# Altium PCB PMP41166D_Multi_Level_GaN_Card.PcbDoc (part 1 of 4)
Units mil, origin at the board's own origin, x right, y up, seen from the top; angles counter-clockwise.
Board outline 3221.72 x 1840 mil, 6 copper layers (Top Layer, Signal Layer 1, Signal Layer 2, Signal Layer 3, Signal Layer 4, Bottom Layer), stack 51.8 mil thick; 155 components, 123 nets, 580 pads, 278 vias.
Unrouted connection lines stored in the file: 2.
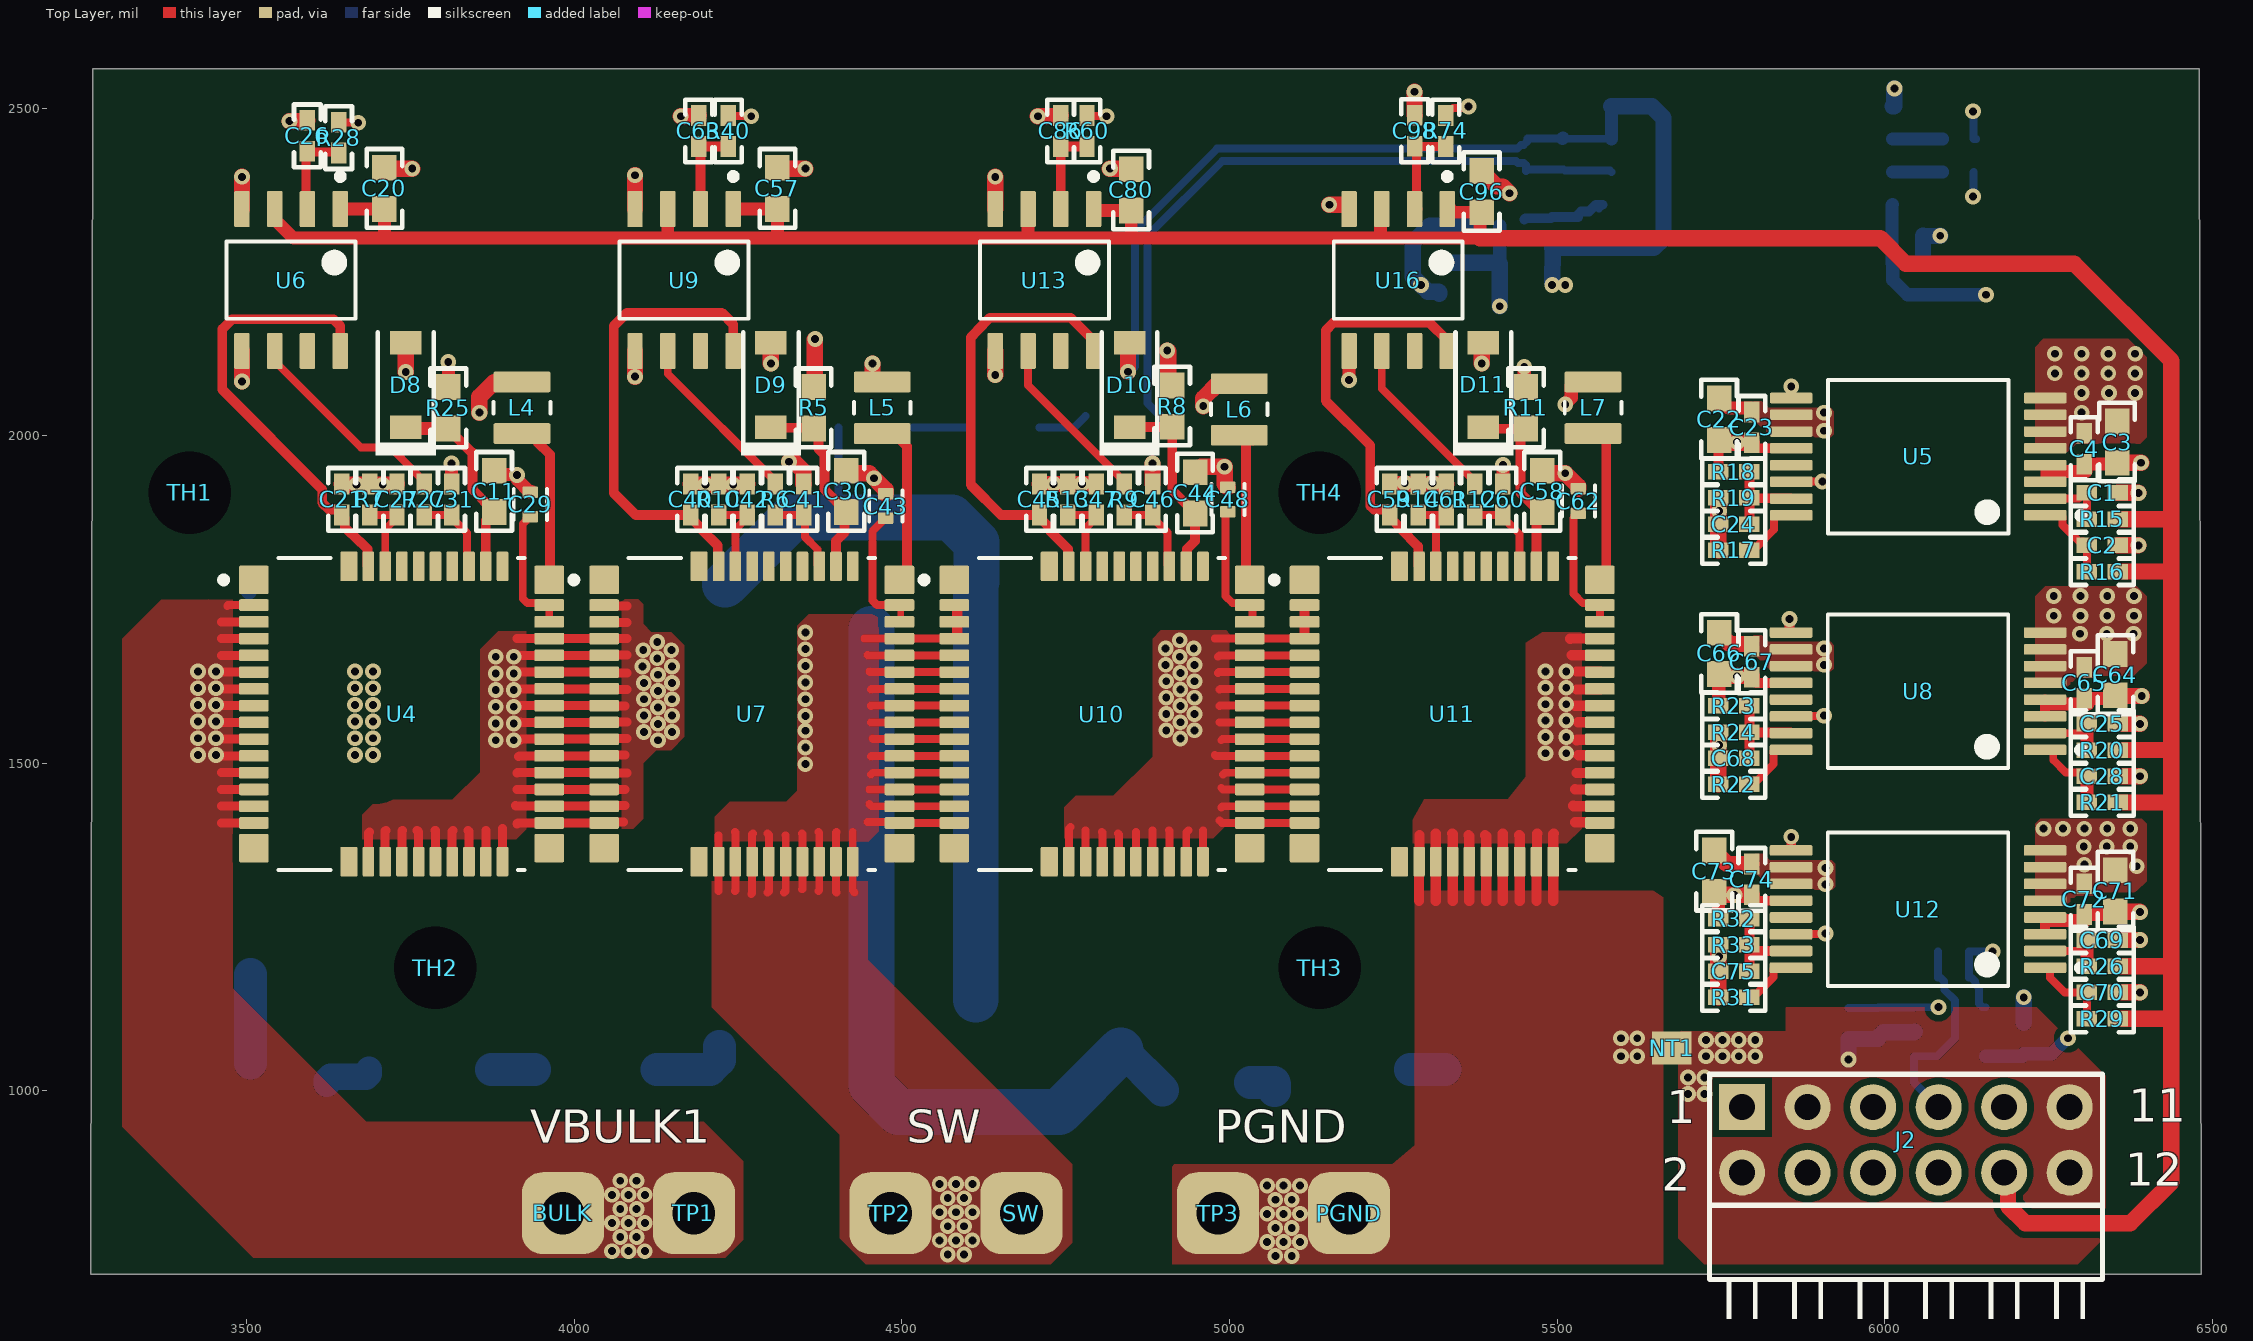
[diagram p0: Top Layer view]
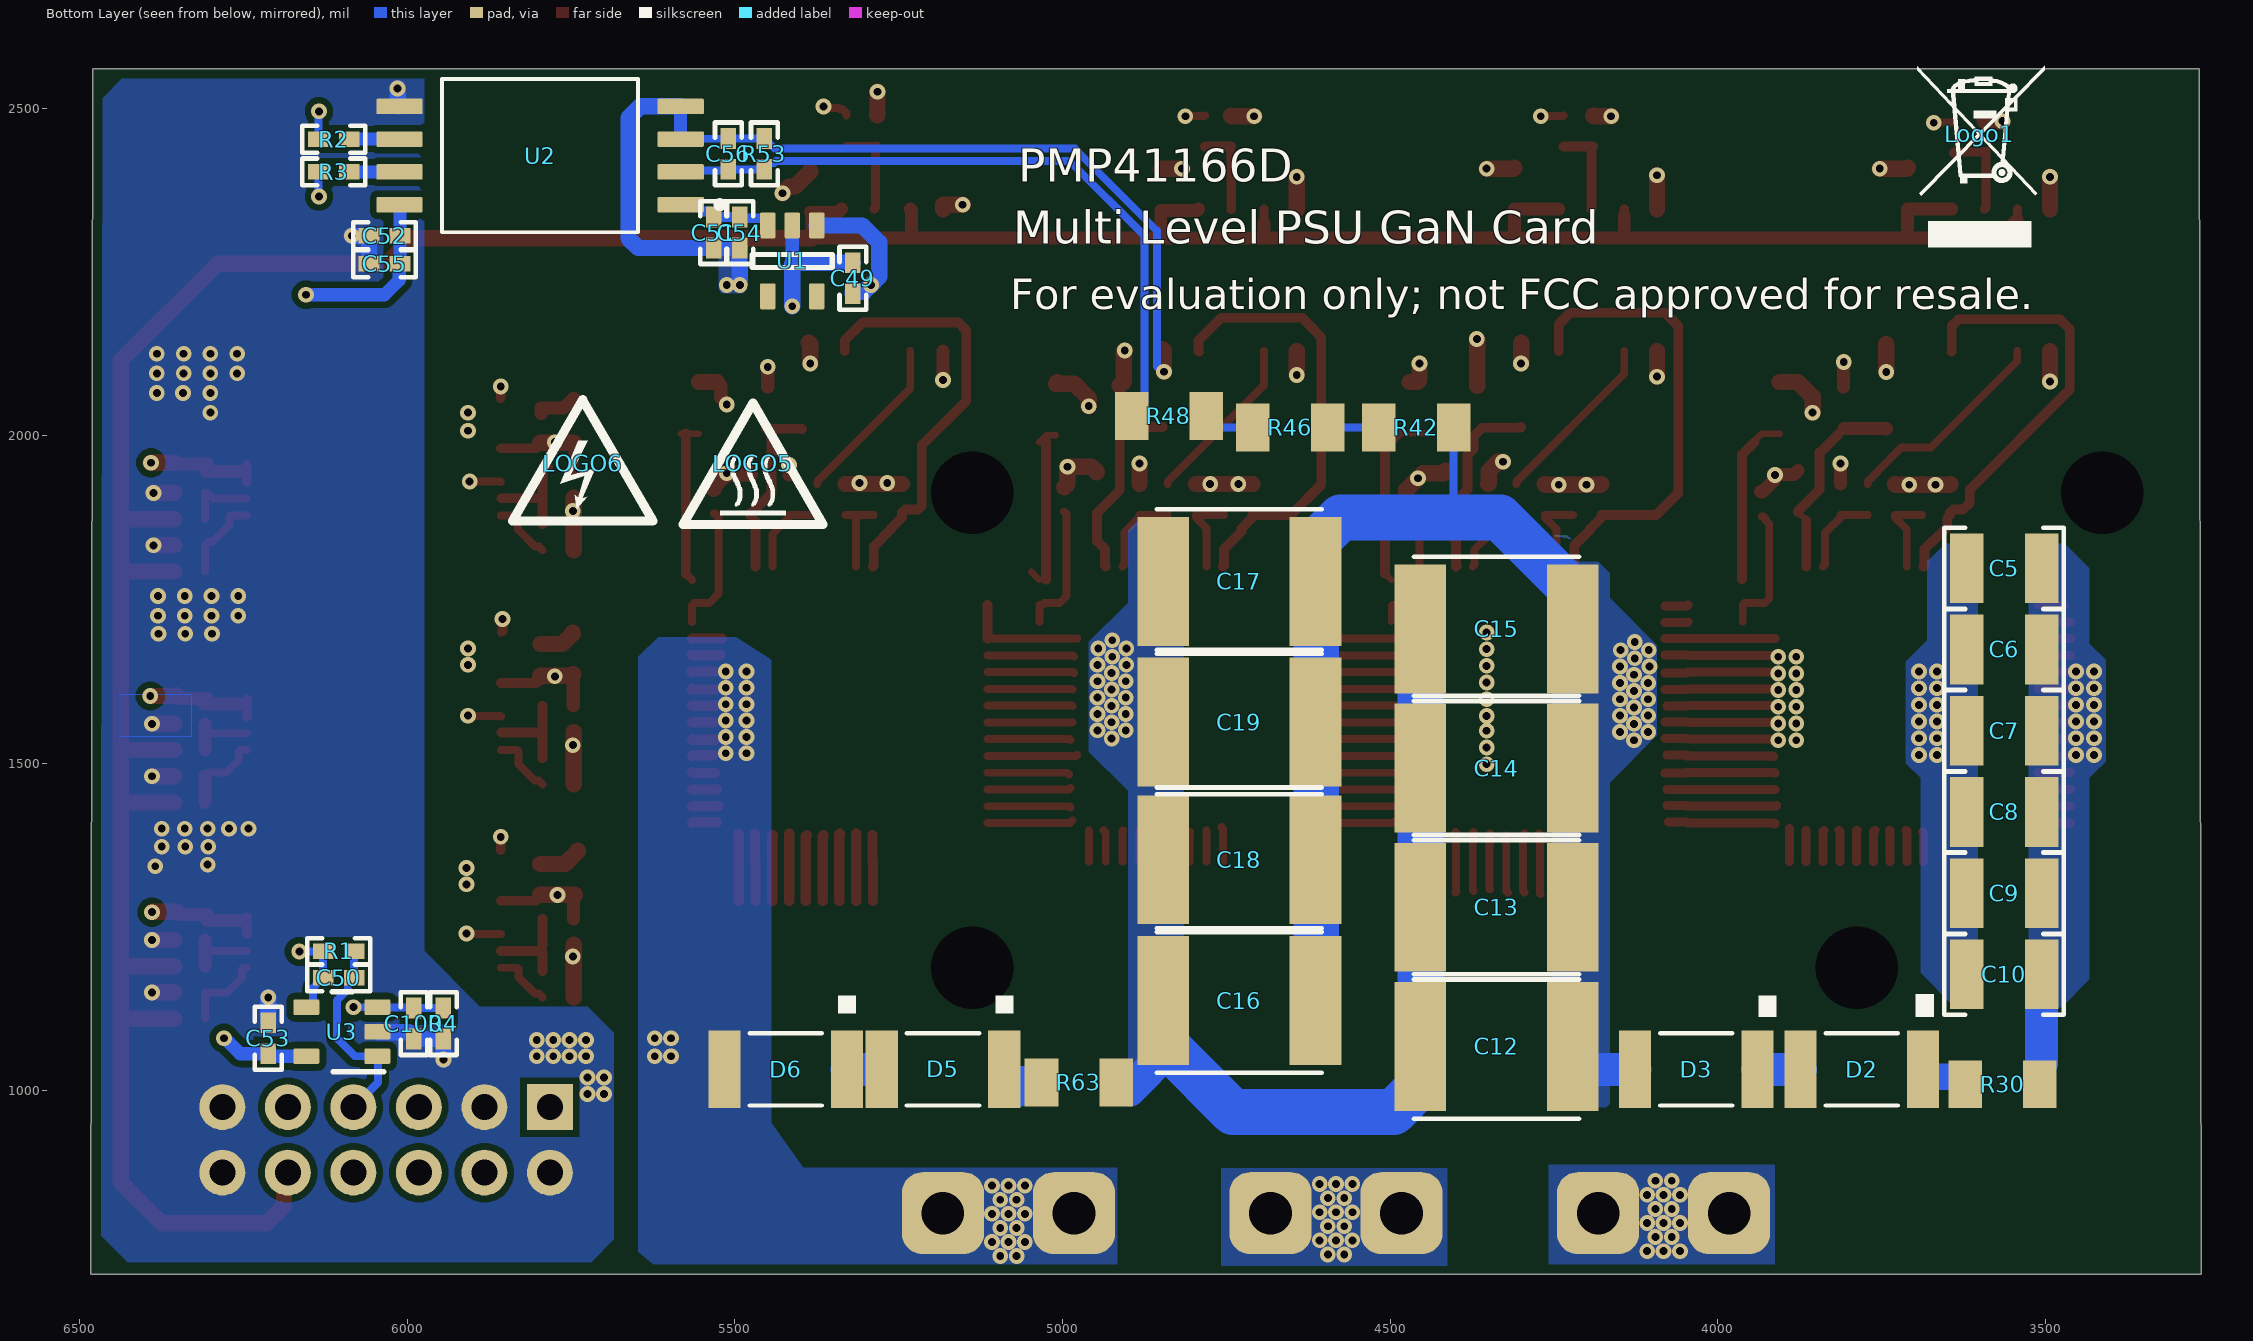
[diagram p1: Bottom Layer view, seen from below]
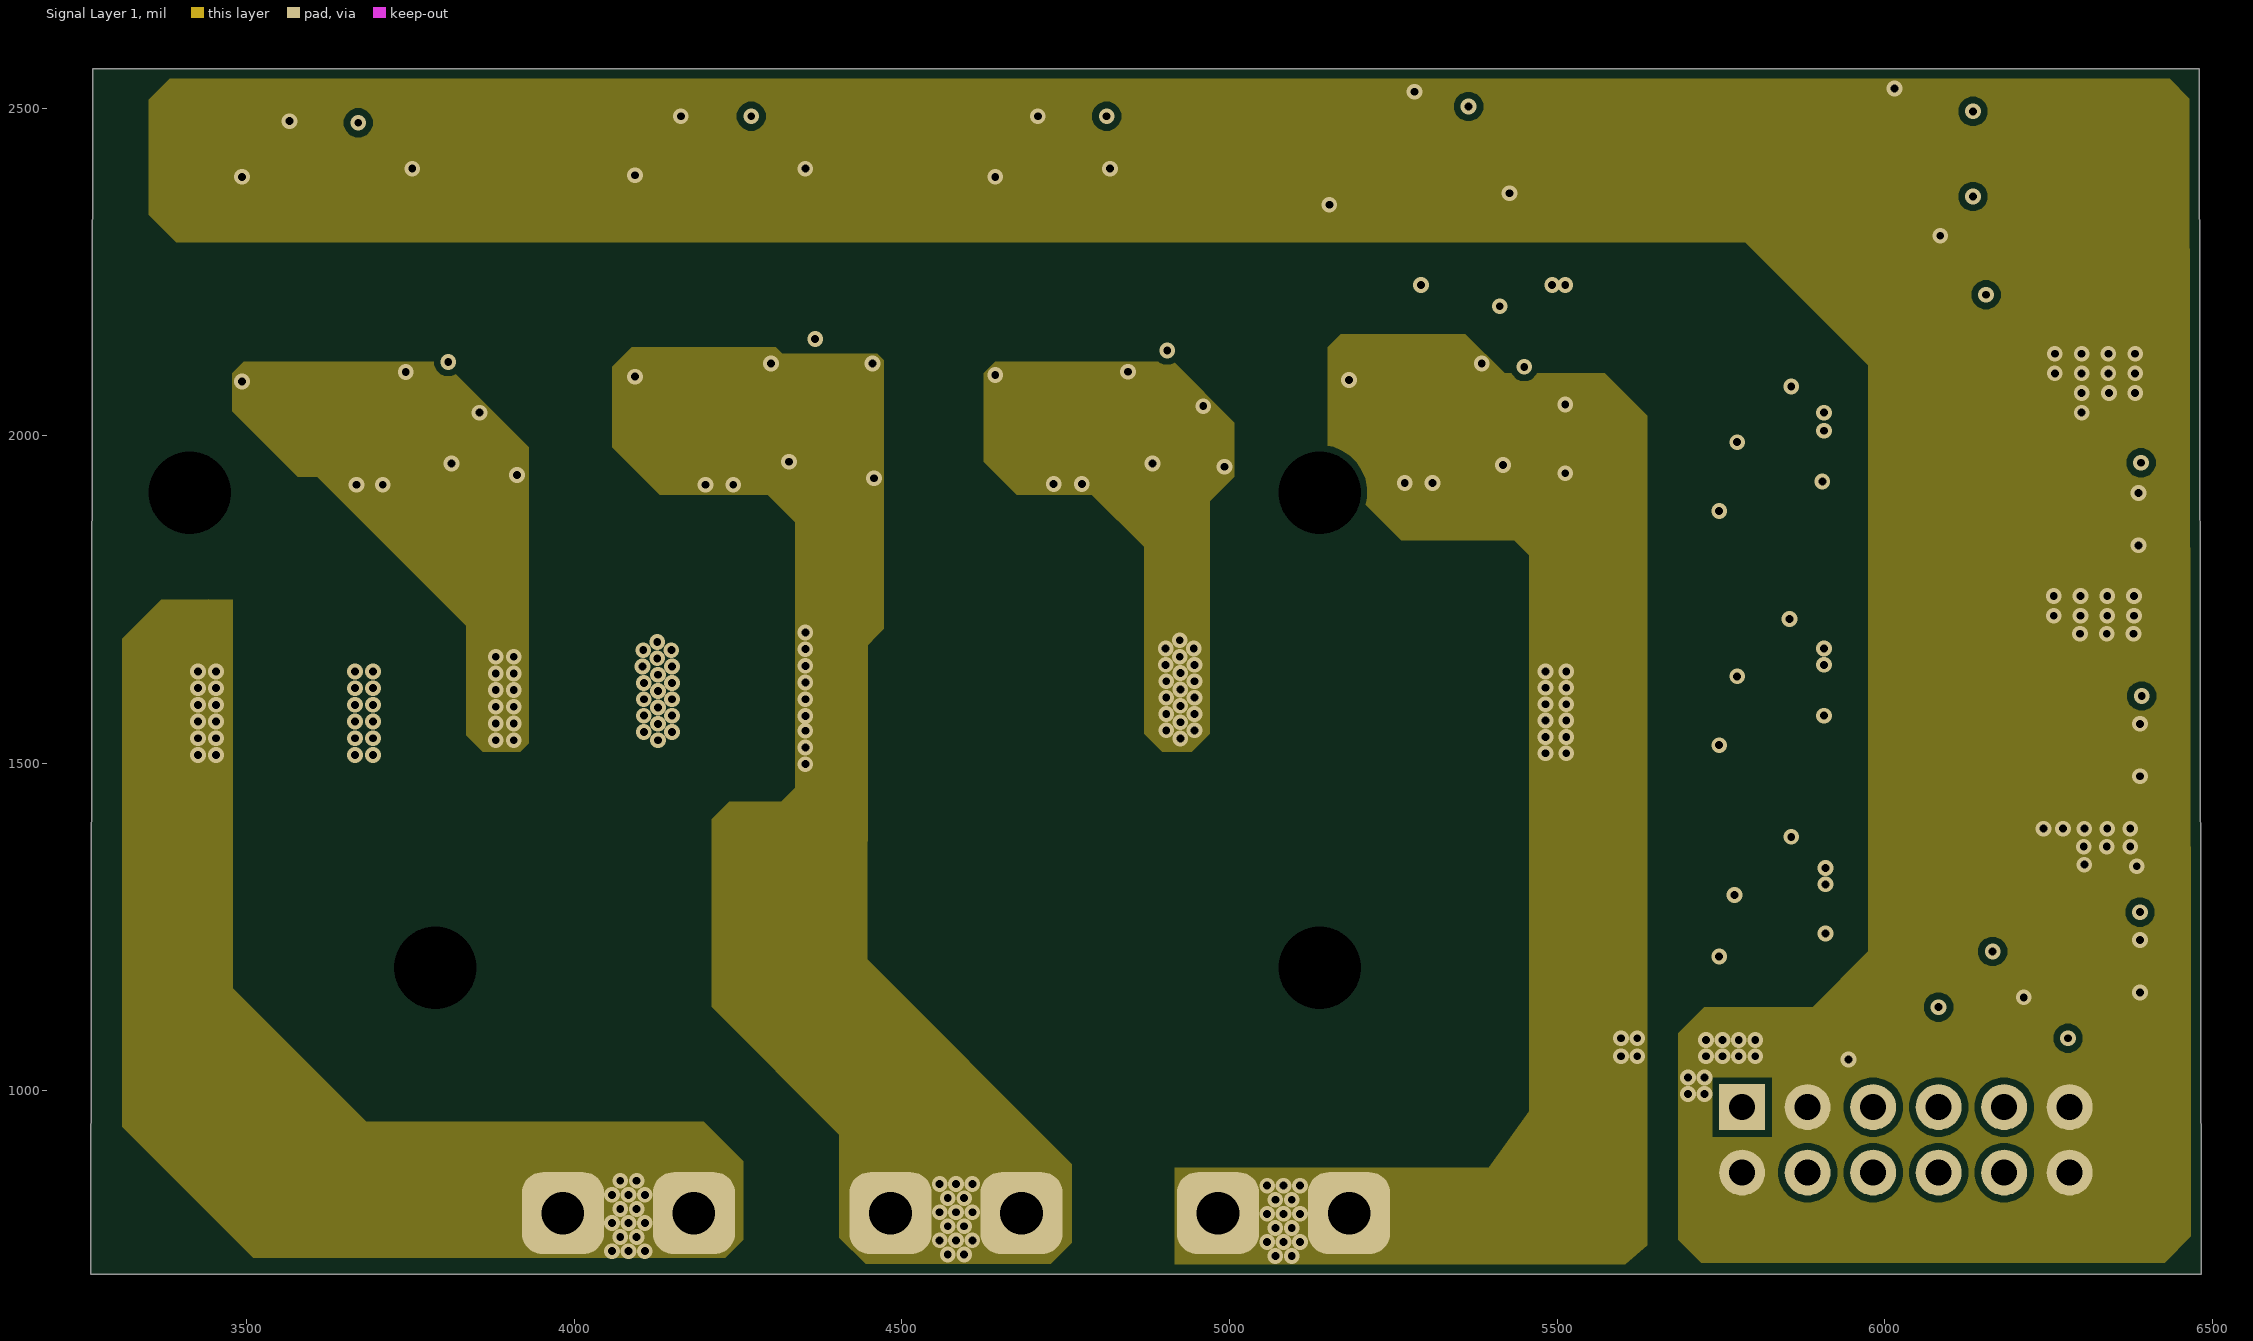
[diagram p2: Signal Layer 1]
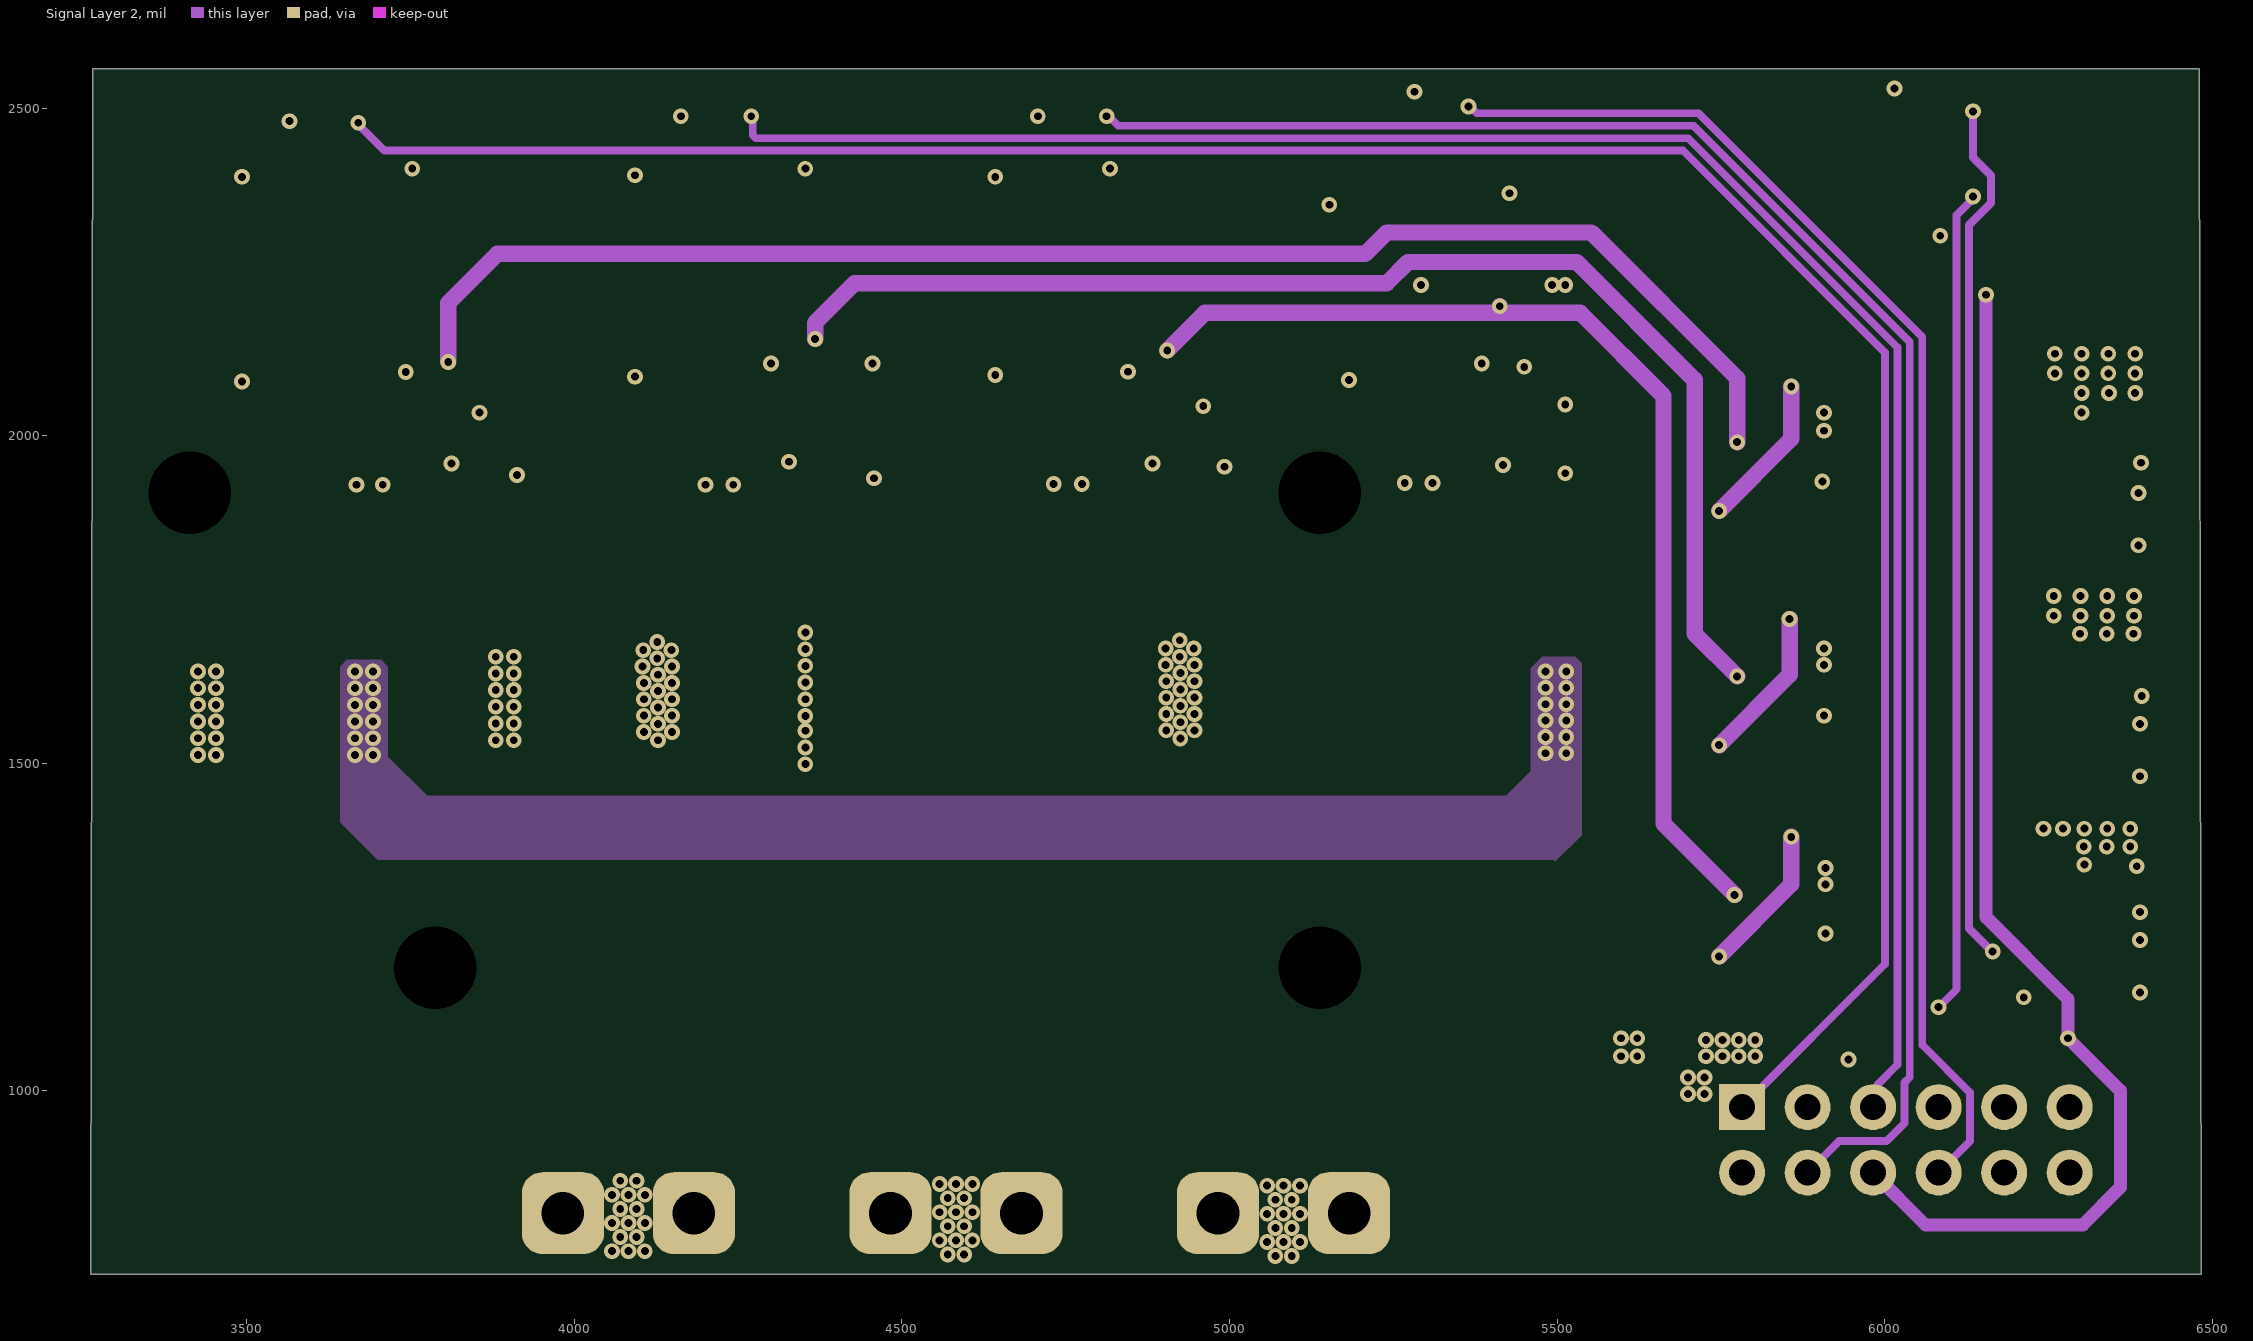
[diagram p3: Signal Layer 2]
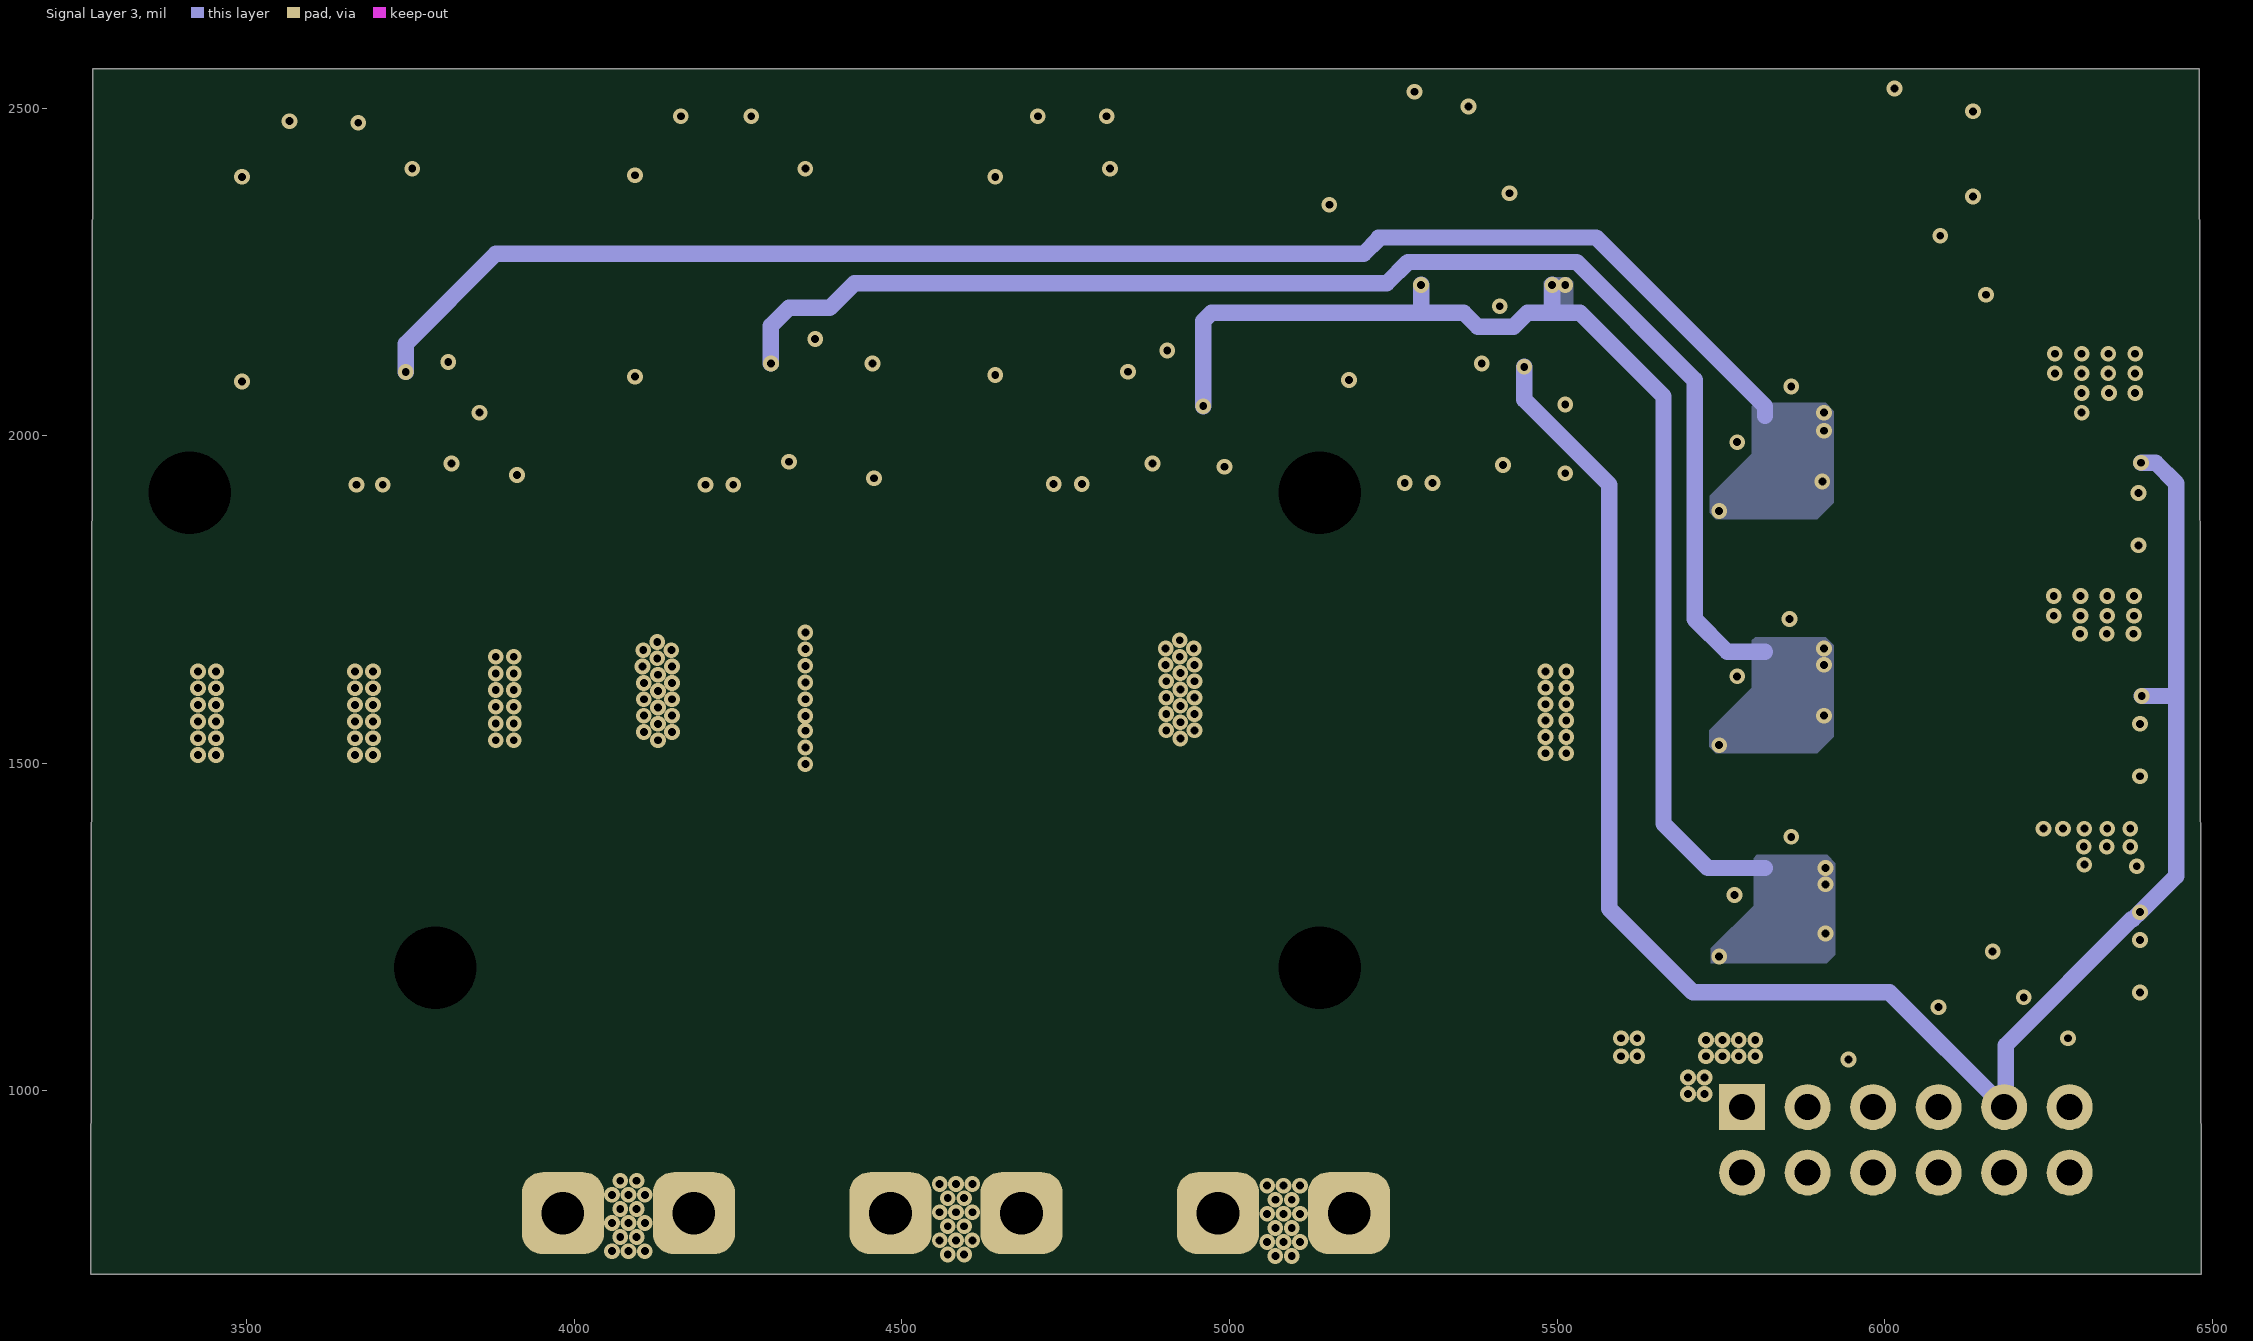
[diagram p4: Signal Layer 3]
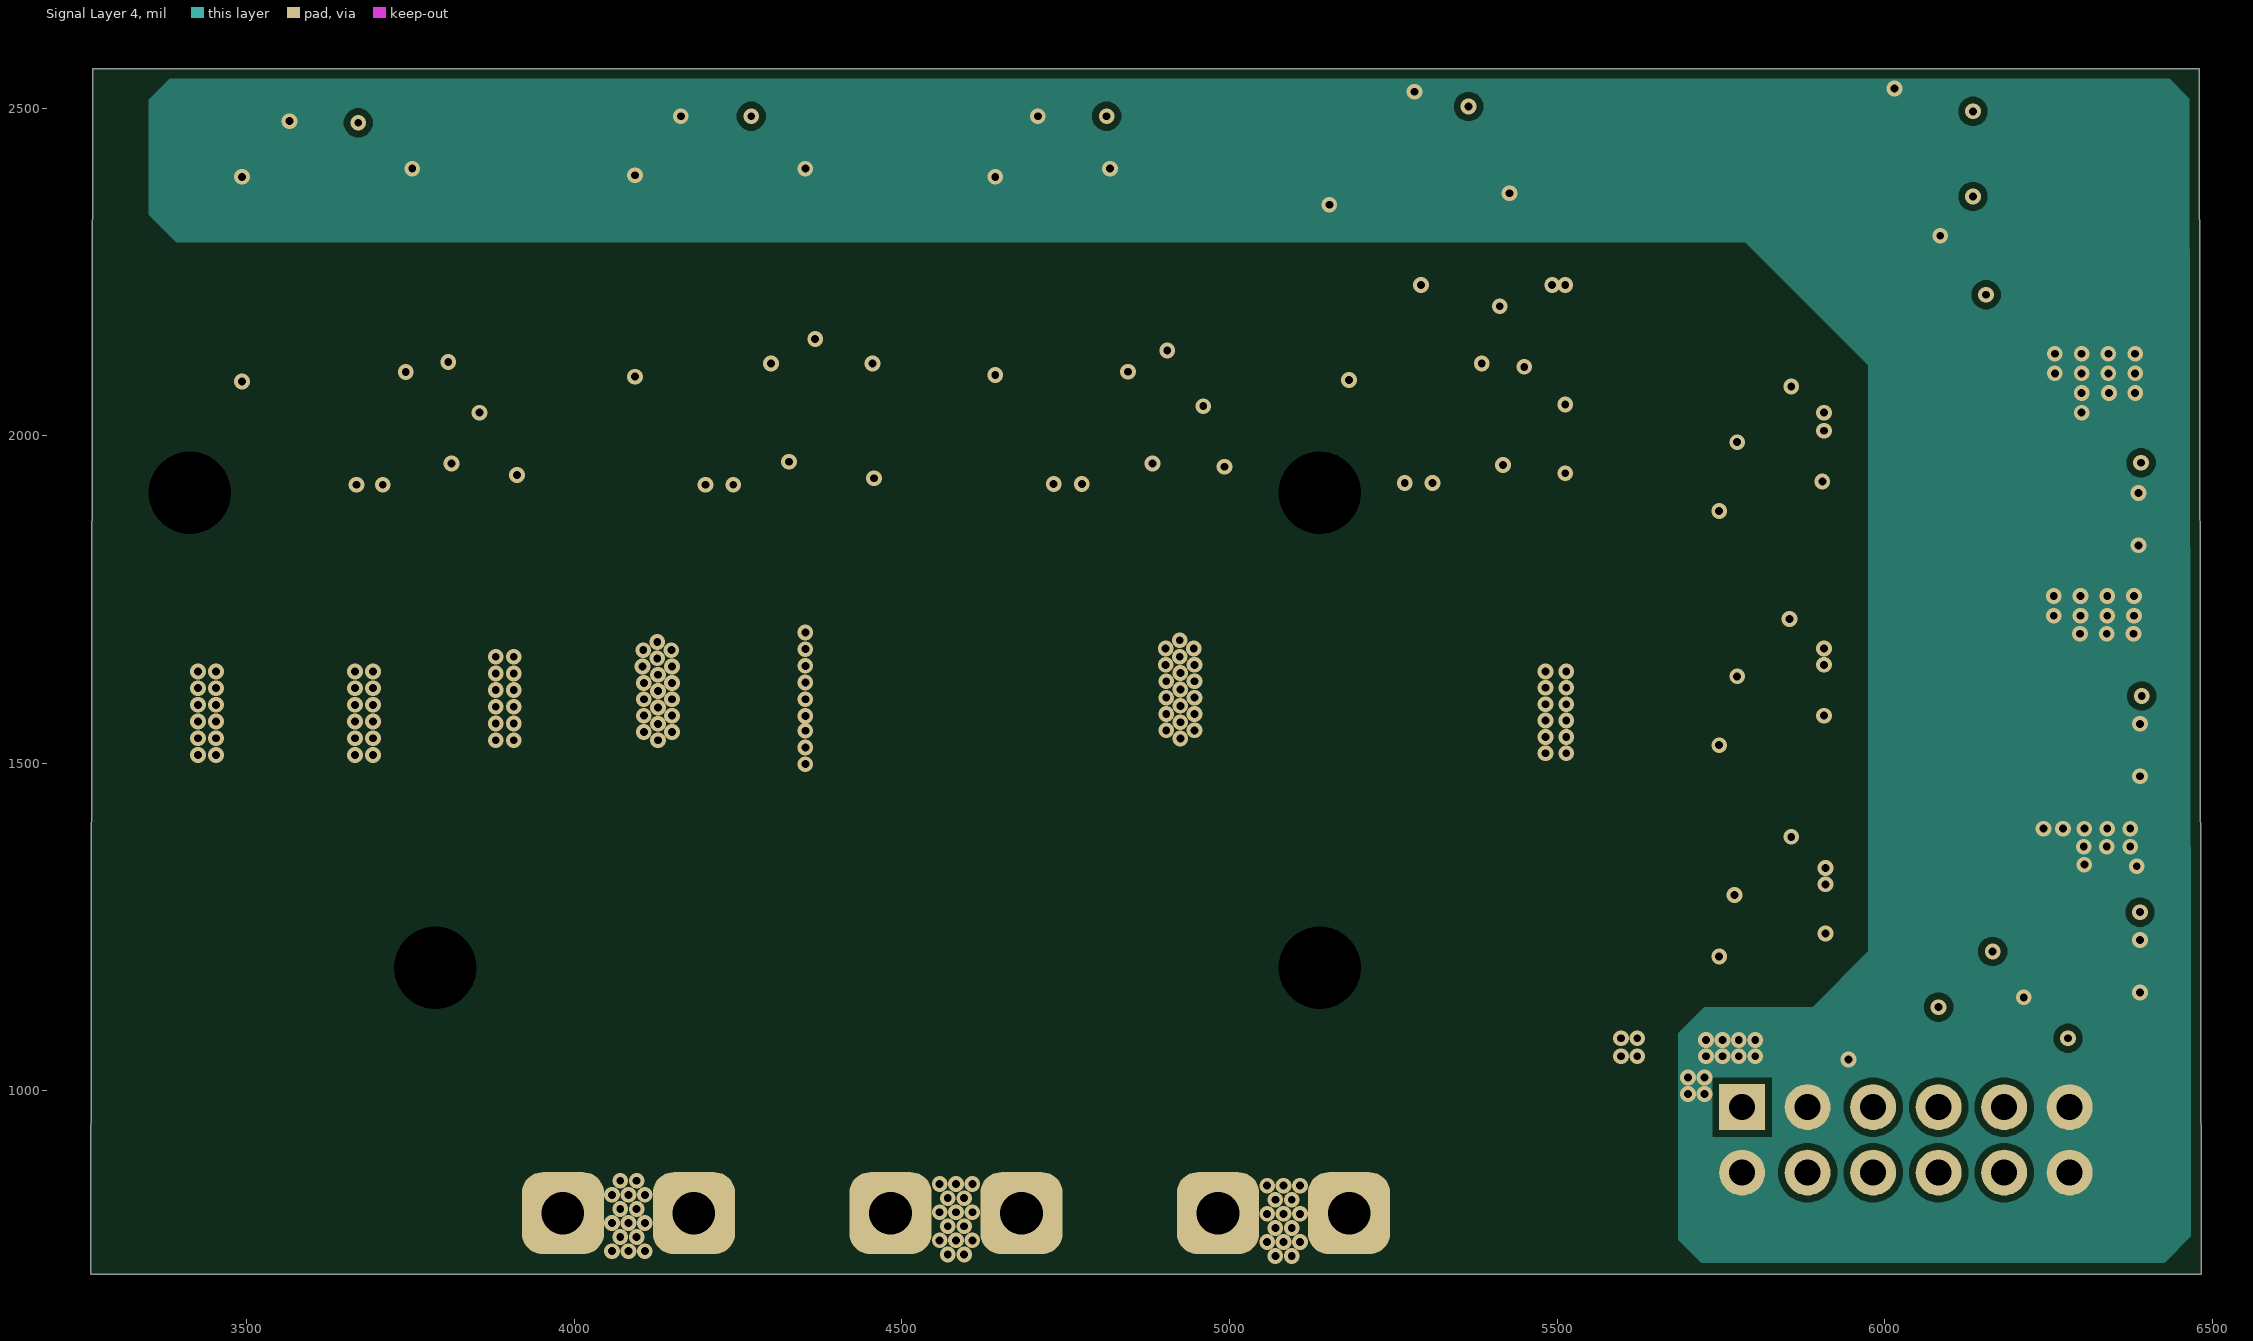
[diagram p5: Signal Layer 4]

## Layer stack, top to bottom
Top Solder: solder mask 0.4, Solder Resist, Dk 3.5
Top Layer: signal copper 2.8
Dielectric 1: prepreg 7, PP-006, Dk 4.1
Signal Layer 1: signal copper 2.8
Dielectric 2: prepreg 7, Dk 4.2
Signal Layer 2: signal copper 2.8
Dielectric3: prepreg 7, FR-4, Dk 4.2
Signal Layer 3: signal copper 2.8
Dielectric 4: prepreg 7, Dk 4.2
Signal Layer 4: signal copper 2.8
Dielectric 5: prepreg 7, PP-006, Dk 4.1
Bottom Layer: signal copper 2.8
Bottom Solder: solder mask 0.4, Solder Resist, Dk 3.5

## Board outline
3261.7,720 6483.42,720 6480.72,2560 3264.4,2560

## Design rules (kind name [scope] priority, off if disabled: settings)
AcuteAngle [All] p1: minimum=4.50000000000000E+0001 checktracksonly=FALSE
AssemblyTestPointUsage [All] p1: valid=2
BoardOutlineClearance BoardOutlineClearance_MountingHoles [OnCopper and InComponentClass('Mounting Holes')] p1: gap=40 ignorepadtopadclearanceinfootprint=FALSE
BoardOutlineClearance BoardOutlineClearance_Poly [OnCopper and IsPoly] p2: gap=15 ignorepadtopadclearanceinfootprint=FALSE
BoardOutlineClearance [OnCopper and Not InComponentClass('Logo') and not InComponentClass('FiducialMark') and not InRegion(1000,500,4000,800) and not InPoly] p3: gap=8 ignorepadtopadclearanceinfootprint=FALSE
Clearance Clearance_TOP [(OnLayer('Top Layer')) And InNetClass('HV') vs InNetClass('LV')] p1: gap=40 ignorepadtopadclearanceinfootprint=TRUE
Clearance "Clearance_Signal Layer1" [(OnLayer('Signal Layer 1')) And InNetClass('HV') vs Not InNetClass('HV')] p2: gap=20 ignorepadtopadclearanceinfootprint=TRUE
Clearance "Clearance_Signal Layer2" [(OnLayer('Signal Layer 2')) And InNetClass('HV') vs Not InNetClass('HV')] p3: gap=31.5 ignorepadtopadclearanceinfootprint=TRUE
Clearance "Clearance_Signal Layer3" [(OnLayer('Signal Layer 3')) And InNetClass('HV') vs Not InNetClass('HV')] p4: gap=31.5 ignorepadtopadclearanceinfootprint=FALSE
Clearance "Clearance_Signal Layer4" [(OnLayer('Signal Layer 4')) And InNetClass('HV') vs Not InNetClass('HV')] p5: gap=31.5 ignorepadtopadclearanceinfootprint=TRUE
Clearance "Clearance_Signal Layer5" [InNetClass('HV') vs Not InNetClass('HV')] p6: gap=10 ignorepadtopadclearanceinfootprint=TRUE
Clearance "Clearance_Signal Layer6" [(OnLayer('Signal Layer 6')) And InNetClass('HV')] p7: gap=31.5 ignorepadtopadclearanceinfootprint=TRUE
Clearance Clearance_BOTTOM [OnLayer('Bottom Layer') And InNetClass('HV') vs Not InNetClass('HV')] p8: gap=40 ignorepadtopadclearanceinfootprint=TRUE
Clearance Clearance_Keepouts [((IsTrack Or IsArc) And Not InPoly) And IsFree and IsKeepOut vs ((IsTrack Or IsArc) And Not InPoly) And IsFree and IsKeepOut] p9: gap=0 ignorepadtopadclearanceinfootprint=FALSE
Clearance Clearance_Poly [InPolygon] p10: gap=10 ignorepadtopadclearanceinfootprint=FALSE
Clearance Clearance_FiducialMark [IsKeepOut and InComponentClass('FiducialMark') vs IsPad and InComponentClass('FiducialMark')] p11: gap=0 ignorepadtopadclearanceinfootprint=FALSE
Clearance [All] p12: gap=7 ignorepadtopadclearanceinfootprint=FALSE
ComponentClearance ComponentClearance_MountingHoles_FiducialMarks [InComponentClass('Mounting Holes') vs InComponentClass('FiducialMark')] p1: gap=50 collisioncheckmode=3 verticalgap=10 showdistances=FALSE
ComponentClearance ComponentClearance_Shunt [InComponentClass('Header') vs InComponentClass('Shunt')] p2: gap=0 collisioncheckmode=3 verticalgap=0 showdistances=FALSE
ComponentClearance ComponentClearance_Logo [InComponentClass('Logo')] p3: gap=10 collisioncheckmode=3 verticalgap=10 showdistances=FALSE
ComponentClearance ComponentClearance_ScrewToNut [(HasFootprint('NY PMS 440 0025 PH')) vs (HasFootprint('Keystone_1902C'))] p4: gap=5 collisioncheckmode=3 verticalgap=10 showdistances=FALSE
ComponentClearance ComponentClearance_MountingHoles [InComponentClass('Mounting Holes')] p5: gap=50 collisioncheckmode=3 verticalgap=100000 showdistances=FALSE
ComponentClearance ComponentClearance_SmallPassives [HasFootprint('0201*') or HasFootprint('0402*') or HasFootprint('0508') or HasFootprint('0603*') or HasFootprint('0612') or HasFootprint('0805*') or HasFootprint('0815*') or HasFootprint('0830*') or HasFootprint('1206*') or HasFootprint('1210*') or HasFootprint('1808*') or HasFootprint('1812*') or HasFootprint('1825*') or HasFootprint('2010*') or HasFootprint('2220*') or HasFootprint('2225*') or HasFootprint('2512*') or HasFootprint('2728*') or HasFootprint('3518*') vs HasFootprint('0201*') or HasFootprint('0402*') or HasFootprint('0508') or HasFootprint('0603*') or HasFootprint('0612') or HasFootprint('0805*') or HasFootprint('0815*') or HasFootprint('0830*') or HasFootprint('1206*') or HasFootprint('1210*') or HasFootprint('1808*') or HasFootprint('1812*') or HasFootprint('1825*') or HasFootprint('2010*') or HasFootprint('2220*') or HasFootprint('2225*') or HasFootprint('2512*') or HasFootprint('2728*') or HasFootprint('3518*')] p6: gap=14.96 collisioncheckmode=3 verticalgap=10 showdistances=FALSE
ComponentClearance ComponentClearance_THtoSMT [IsThruComponent vs IsSMTComponent] p7: gap=10 collisioncheckmode=3 verticalgap=10 showdistances=FALSE
ComponentClearance ComponentClearance_THtoTH [IsThruComponent vs IsThruComponent] p8: gap=10 collisioncheckmode=3 verticalgap=10 showdistances=FALSE
ComponentClearance [All] p9: gap=10 collisioncheckmode=3 verticalgap=10 showdistances=FALSE
DiffPairsRouting [All] p1: maxlimit=100 minlimit=10 mostfreqgap=10 toplayer_minwidth=15 toplayer_maxwidth=15 toplayer_prefwidth=15 midlayer1_minwidth=15 midlayer1_maxwidth=15 midlayer1_prefwidth=15 midlayer4_minwidth=15 midlayer4_maxwidth=15 midlayer4_prefwidth=15 midlayer5_minwidth=15 midlayer5_maxwidth=15 midlayer5_prefwidth=15 midlayer6_minwidth=15 midlayer6_maxwidth=15 midlayer6_prefwidth=15 bottomlayer_minwidth=15 bottomlayer_maxwidth=15 bottomlayer_prefwidth=15 maxuncoupledlength=1000
FabricationTestPointUsage TestPointUsage [All] p1: valid=2 allowmultiple=FALSE
FabricationTestpoint Testpoint [All] p1: side=3 testpointundercomponent=TRUE minsize=40 maxsize=100 preferedsize=60 minholesize=0 maxholesize=40 preferedholesize=32 testpointgrid=1 allowsidetop=TRUE allowsidebottom=TRUE usegrid=TRUE gridtolerance=0.01
FanoutControl Fanout_LCC [IsLCC] p1: bgadir=Out bgaviamode=Centered fanoutstyle=Auto fanoutdirection=Alternating viagrid=1 // Fanout_LCC (Default Rule)
FanoutControl Fanout_BGA [IsBGA] p2: bgadir=Out bgaviamode=Centered fanoutstyle=Auto fanoutdirection=Alternating viagrid=1 // Fanout_BGA (Default Rule)
FanoutControl Fanout_Default [All] p4: bgadir=Out bgaviamode=Centered fanoutstyle=Auto fanoutdirection=Alternating viagrid=1 // Fanout_Default (Default Rule)
FanoutControl Fanout_Small [(CompPinCount < 5)] p5: bgadir=Out bgaviamode=Centered fanoutstyle=Auto fanoutdirection=OutThenIn viagrid=1 // Fanout_Small (Default Rule)
Height [All] p1: minheight=0 maxheight=1500 prefheight=500
HoleSize [All] p1: absolutevalues=TRUE maxlimit=500 minlimit=7.87 maxpercent=80.000 minpercent=20.000
HoleToHoleClearance [All] p1: gap=0 allowstackedmicrovias=TRUE
MinimumAnnularRing MinimumAnnularRing_ThermalPadVias [IsVia and InAnyComponent] p1: minimumring=5.91
MinimumAnnularRing [All] p2: minimumring=5
MinimumSolderMaskSliver MinimumSolderMaskSliver_Logo [InComponentClass('Logo') vs InComponentClass('Logo')] p1: minsoldermaskwidth=0.7
MinimumSolderMaskSliver [All] p2: minsoldermaskwidth=3.94
PlaneConnect [All] p1: planeconnectstyle=Relief reliefexpansion=10 reliefentries=4 reliefconductorwidth=10 reliefairgap=10
PolygonConnect PolygonConnect_59 [All vs IsNamedPolygon('PGND') Or  IsNamedPolygon('C102_1') Or  IsNamedPolygon('PGND') Or  IsNamedPolygon('F150_2') Or  IsNamedPolygon('C102_1') Or  IsNamedPolygon('F150_1') Or  IsNamedPolygon('C105_2') Or  IsNamedPolygon('ZCD') Or  IsNamedPolygon('C102_1') Or  IsNamedPolygon('C102_1') Or  IsNamedPolygon('PGND') Or  IsNamedPolygon('PGND') Or  IsNamedPolygon('Line') Or  IsNamedPolygon('F150_1') Or  IsNamedPolygon('ZCD') Or  IsNamedPolygon('Line') Or  IsNamedPolygon('Neutral') Or  IsNamedPolygon('F150_2') Or  IsNamedPolygon('Line') Or  IsNamedPolygon('Neutral') Or  IsNamedPolygon('F150_1') Or  IsNamedPolygon('PGND') Or  IsNamedPolygon('SWNODE') Or  IsNamedPolygon('SWNODE') Or  IsNamedPolygon('SWNODE') Or  IsNamedPolygon('PGND') Or  IsNamedPolygon('Line') Or  IsNamedPolygon('Vbulk1') Or  IsNamedPolygon('C105_2') Or  IsNamedPolygon('PGND') Or  IsNamedPolygon('C105_2') Or  IsNamedPolygon('PGND') Or  IsNamedPolygon('C105_1') Or  IsNamedPolygon('PGND') Or  IsNamedPolygon('Vbulk') Or  IsNamedPolygon('Vbulk') Or  IsNamedPolygon('F150_1') Or  IsNamedPolygon('Vbulk') Or  IsNamedPolygon('PGND') Or  IsNamedPolygon('C105_1') Or  IsNamedPolygon('Neutral') Or  IsNamedPolygon('Neutral') Or  IsNamedPolygon('SWNODE') Or  IsNamedPolygon('C102_1') Or  IsNamedPolygon('F150_2') Or  IsNamedPolygon('C105_1') Or  IsNamedPolygon('Line') Or  IsNamedPolygon('F150_2') Or  IsNamedPolygon('F150_2') Or  IsNamedPolygon('F150_1') Or  IsNamedPolygon('C105_1') Or  IsNamedPolygon('Vbulk1') Or  IsNamedPolygon('PGND') Or  IsNamedPolygon('C105_2') Or  IsNamedPolygon('F150_1') Or  IsNamedPolygon('C105_1') Or  IsNamedPolygon('F150_2') Or  IsNamedPolygon('C102_1') Or  IsNamedPolygon('PGND') Or  IsNamedPolygon('VBB') Or  IsNamedPolygon('12Vp') Or  IsNamedPolygon('J102_1') Or  IsNamedPolygon('J102_1') Or  IsNamedPolygon('Neutral') Or  IsNamedPolygon('Neutral') Or  IsNamedPolygon('PGND') Or  IsNamedPolygon('VBB') Or  IsNamedPolygon('Vbulk') Or  IsNamedPolygon('VBB') Or  IsNamedPolygon('C105_2') Or  IsNamedPolygon('ZCD') Or  IsNamedPolygon('C105_2') Or  IsNamedPolygon('ZCD') Or  IsNamedPolygon('Vbulk') Or  IsNamedPolygon('ZCD') Or  IsNamedPolygon('5Vp') Or  IsNamedPolygon('J102_1') Or  IsNamedPolygon('SWNODE') Or  IsNamedPolygon('PGND') Or  IsNamedPolygon('ZCD') Or  IsNamedPolygon('D106_1') Or  IsNamedPolygon('VBB') Or  IsNamedPolygon('J102_1') Or  IsNamedPolygon('J102_1') Or  IsNamedPolygon('PGND') Or  IsNamedPolygon('VBB') Or  IsNamedPolygon('D106_1') Or  IsNamedPolygon('PGND') Or  IsNamedPolygon('SWNODE') Or  IsNamedPolygon('ZCD') Or  IsNamedPolygon('PGND') Or  IsNamedPolygon('Vbulk1') Or  IsNamedPolygon('ZCD') Or  IsNamedPolygon('Line') Or  IsNamedPolygon('Vbulk') Or  IsNamedPolygon('PGND') Or  IsNamedPolygon('PGND') Or  IsNamedPolygon('VBB') Or  IsNamedPolygon('PGND') Or  IsNamedPolygon('C105_1') Or  IsNamedPolygon('VBB') Or  IsNamedPolygon('ZCD') Or  IsNamedPolygon('Neutral') Or  IsNamedPolygon('ZCD') Or  IsNamedPolygon('PE') Or  IsNamedPolygon('J102_1') Or  IsNamedPolygon('Vbulk') Or  IsNamedPolygon('Vbulk1')] p1: connectstyle=Direct reliefconductorwidth=10 reliefentries=4 polygonreliefangle="90 Angle" airgapwidth=10
PolygonConnect PolygonConnect_58 [All vs IsNamedPolygon('C105_1') Or  IsNamedPolygon('12Vp') Or  IsNamedPolygon('Neutral') Or  IsNamedPolygon('C105_2') Or  IsNamedPolygon('ZCD') Or  IsNamedPolygon('C105_1') Or  IsNamedPolygon('VBB') Or  IsNamedPolygon('PGND') Or  IsNamedPolygon('F150_2') Or  IsNamedPolygon('SWNODE') Or  IsNamedPolygon('PGND') Or  IsNamedPolygon('PGND') Or  IsNamedPolygon('J102_1') Or  IsNamedPolygon('D106_1') Or  IsNamedPolygon('PGND') Or  IsNamedPolygon('C105_2') Or  IsNamedPolygon('SWNODE') Or  IsNamedPolygon('Vbulk') Or  IsNamedPolygon('PGND') Or  IsNamedPolygon('PGND') Or  IsNamedPolygon('PGND') Or  IsNamedPolygon('PGND') Or  IsNamedPolygon('Vbulk') Or  IsNamedPolygon('PGND') Or  IsNamedPolygon('PGND') Or  IsNamedPolygon('D106_1') Or  IsNamedPolygon('Neutral') Or  IsNamedPolygon('PGND') Or  IsNamedPolygon('C105_2') Or  IsNamedPolygon('Vbulk') Or  IsNamedPolygon('SWNODE') Or  IsNamedPolygon('VBB') Or  IsNamedPolygon('J102_1') Or  IsNamedPolygon('VBB') Or  IsNamedPolygon('PGND') Or  IsNamedPolygon('5Vp') Or  IsNamedPolygon('SWNODE') Or  IsNamedPolygon('C105_1') Or  IsNamedPolygon('VBB') Or  IsNamedPolygon('SWNODE') Or  IsNamedPolygon('ZCD') Or  IsNamedPolygon('Vbulk') Or  IsNamedPolygon('Line') Or  IsNamedPolygon('Vbulk1') Or  IsNamedPolygon('PGND') Or  IsNamedPolygon('ZCD') Or  IsNamedPolygon('VBB') Or  IsNamedPolygon('PGND') Or  IsNamedPolygon('ZCD') Or  IsNamedPolygon('Vbulk1') Or  IsNamedPolygon('Neutral') Or  IsNamedPolygon('F150_2') Or  IsNamedPolygon('F150_2') Or  IsNamedPolygon('PGND') Or  IsNamedPolygon('Neutral') Or  IsNamedPolygon('C102_1') Or  IsNamedPolygon('C105_1') Or  IsNamedPolygon('Line') Or  IsNamedPolygon('J102_1') Or  IsNamedPolygon('Neutral') Or  IsNamedPolygon('Neutral') Or  IsNamedPolygon('SWNODE') Or  IsNamedPolygon('ZCD') Or  IsNamedPolygon('J102_1') Or  IsNamedPolygon('J102_1') Or  IsNamedPolygon('PGND') Or  IsNamedPolygon('ZCD') Or  IsNamedPolygon('Vbulk') Or  IsNamedPolygon('Line') Or  IsNamedPolygon('VBB') Or  IsNamedPolygon('Vbulk') Or  IsNamedPolygon('VBB') Or  IsNamedPolygon('Line') Or  IsNamedPolygon('C105_1') Or  IsNamedPolygon('ZCD') Or  IsNamedPolygon('C105_2') Or  IsNamedPolygon('Line') Or  IsNamedPolygon('C105_2') Or  IsNamedPolygon('PGND') Or  IsNamedPolygon('PE') Or  IsNamedPolygon('Neutral') Or  IsNamedPolygon('F150_2') Or  IsNamedPolygon('ZCD') Or  IsNamedPolygon('F150_2') Or  IsNamedPolygon('F150_2') Or  IsNamedPolygon('ZCD') Or  IsNamedPolygon('PGND') Or  IsNamedPolygon('PGND') Or  IsNamedPolygon('Vbulk1') Or  IsNamedPolygon('Line') Or  IsNamedPolygon('ZCD') Or  IsNamedPolygon('C105_1') Or  IsNamedPolygon('J102_1') Or  IsNamedPolygon('Vbulk1') Or  IsNamedPolygon('Vbulk') Or  IsNamedPolygon('C105_2') Or  IsNamedPolygon('PGND')] p2: connectstyle=Direct reliefconductorwidth=10 reliefentries=4 polygonreliefangle="90 Angle" airgapwidth=10
PolygonConnect PolygonConnect_57 [All vs IsNamedPolygon('PGND') Or  IsNamedPolygon('C105_2') Or  IsNamedPolygon('VBB') Or  IsNamedPolygon('5Vp') Or  IsNamedPolygon('ZCD') Or  IsNamedPolygon('J102_1') Or  IsNamedPolygon('PGND') Or  IsNamedPolygon('PGND') Or  IsNamedPolygon('PGND') Or  IsNamedPolygon('PE') Or  IsNamedPolygon('VBB') Or  IsNamedPolygon('VBB') Or  IsNamedPolygon('ZCD') Or  IsNamedPolygon('ZCD') Or  IsNamedPolygon('Line') Or  IsNamedPolygon('PGND') Or  IsNamedPolygon('C102_1') Or  IsNamedPolygon('VBB') Or  IsNamedPolygon('J102_1') Or  IsNamedPolygon('Vbulk') Or  IsNamedPolygon('PGND') Or  IsNamedPolygon('Neutral') Or  IsNamedPolygon('Vbulk') Or  IsNamedPolygon('ZCD') Or  IsNamedPolygon('J102_1') Or  IsNamedPolygon('PGND') Or  IsNamedPolygon('ZCD') Or  IsNamedPolygon('J102_1') Or  IsNamedPolygon('VBB') Or  IsNamedPolygon('Neutral') Or  IsNamedPolygon('PGND') Or  IsNamedPolygon('PGND') Or  IsNamedPolygon('12Vp') Or  IsNamedPolygon('Vbulk') Or  IsNamedPolygon('PGND') Or  IsNamedPolygon('Vbulk') Or  IsNamedPolygon('J102_1') Or  IsNamedPolygon('PGND') Or  IsNamedPolygon('D106_1') Or  IsNamedPolygon('PGND') Or  IsNamedPolygon('Vbulk1') Or  IsNamedPolygon('PGND') Or  IsNamedPolygon('C105_2') Or  IsNamedPolygon('Vbulk') Or  IsNamedPolygon('Neutral') Or  IsNamedPolygon('Vbulk1') Or  IsNamedPolygon('PGND') Or  IsNamedPolygon('PGND') Or  IsNamedPolygon('J102_1') Or  IsNamedPolygon('SWNODE') Or  IsNamedPolygon('Vbulk1') Or  IsNamedPolygon('C105_2') Or  IsNamedPolygon('VBB') Or  IsNamedPolygon('VBB') Or  IsNamedPolygon('ZCD') Or  IsNamedPolygon('SWNODE') Or  IsNamedPolygon('Vbulk') Or  IsNamedPolygon('PGND') Or  IsNamedPolygon('Vbulk') Or  IsNamedPolygon('C105_1') Or  IsNamedPolygon('PGND') Or  IsNamedPolygon('PGND') Or  IsNamedPolygon('ZCD') Or  IsNamedPolygon('C105_2') Or  IsNamedPolygon('D106_1') Or  IsNamedPolygon('PGND') Or  IsNamedPolygon('C105_2') Or  IsNamedPolygon('C105_2') Or  IsNamedPolygon('ZCD') Or  IsNamedPolygon('PGND')] p3: connectstyle=Direct reliefconductorwidth=10 reliefentries=4 polygonreliefangle="90 Angle" airgapwidth=10
PolygonConnect PolygonConnect_56 [All vs IsNamedPolygon('PGND') Or  IsNamedPolygon('C105_2') Or  IsNamedPolygon('VBB') Or  IsNamedPolygon('5Vp') Or  IsNamedPolygon('ZCD') Or  IsNamedPolygon('J102_1') Or  IsNamedPolygon('PGND') Or  IsNamedPolygon('PGND') Or  IsNamedPolygon('PGND') Or  IsNamedPolygon('PE') Or  IsNamedPolygon('VBB') Or  IsNamedPolygon('VBB') Or  IsNamedPolygon('ZCD') Or  IsNamedPolygon('ZCD') Or  IsNamedPolygon('Line') Or  IsNamedPolygon('PGND') Or  IsNamedPolygon('C102_1') Or  IsNamedPolygon('VBB') Or  IsNamedPolygon('J102_1') Or  IsNamedPolygon('Vbulk') Or  IsNamedPolygon('PGND') Or  IsNamedPolygon('Neutral') Or  IsNamedPolygon('Vbulk') Or  IsNamedPolygon('ZCD') Or  IsNamedPolygon('J102_1') Or  IsNamedPolygon('PGND') Or  IsNamedPolygon('ZCD') Or  IsNamedPolygon('J102_1') Or  IsNamedPolygon('VBB') Or  IsNamedPolygon('Neutral') Or  IsNamedPolygon('PGND') Or  IsNamedPolygon('PGND') Or  IsNamedPolygon('12Vp') Or  IsNamedPolygon('Vbulk') Or  IsNamedPolygon('PGND') Or  IsNamedPolygon('Vbulk') Or  IsNamedPolygon('J102_1') Or  IsNamedPolygon('PGND') Or  IsNamedPolygon('D106_1') Or  IsNamedPolygon('PGND') Or  IsNamedPolygon('Vbulk1') Or  IsNamedPolygon('PGND') Or  IsNamedPolygon('C105_2') Or  IsNamedPolygon('Vbulk') Or  IsNamedPolygon('Neutral') Or  IsNamedPolygon('Vbulk1') Or  IsNamedPolygon('PGND') Or  IsNamedPolygon('PGND') Or  IsNamedPolygon('J102_1') Or  IsNamedPolygon('SWNODE') Or  IsNamedPolygon('Vbulk1') Or  IsNamedPolygon('C105_2') Or  IsNamedPolygon('VBB') Or  IsNamedPolygon('VBB') Or  IsNamedPolygon('ZCD') Or  IsNamedPolygon('SWNODE') Or  IsNamedPolygon('Vbulk') Or  IsNamedPolygon('PGND') Or  IsNamedPolygon('Vbulk') Or  IsNamedPolygon('C105_1') Or  IsNamedPolygon('PGND') Or  IsNamedPolygon('PGND') Or  IsNamedPolygon('ZCD') Or  IsNamedPolygon('C105_2') Or  IsNamedPolygon('D106_1') Or  IsNamedPolygon('PGND') Or  IsNamedPolygon('C105_2') Or  IsNamedPolygon('C105_2') Or  IsNamedPolygon('ZCD') Or  IsNamedPolygon('PGND')] p4: thpad.connectstyle=Direct thpad.reliefconductorwidth=10 thpad.reliefentries=4 thpad.polygonreliefangle="90 Angle" thpad.airgapwidth=10 smdpad.connectstyle=Relief smdpad.reliefconductorwidth=10 smdpad.reliefentries=4 smdpad.polygonreliefangle="90 Angle" smdpad.airgapwidth=10 via.connectstyle=Relief via.reliefconductorwidth=10 via.reliefentries=4 via.polygonreliefangle="90 Angle" via.airgapwidth=10
PolygonConnect PolygonConnect_55 [All vs IsNamedPolygon('SWNODE') Or  IsNamedPolygon('ZCD') Or  IsNamedPolygon('PGND') Or  IsNamedPolygon('PGND') Or  IsNamedPolygon('PGND') Or  IsNamedPolygon('PGND') Or  IsNamedPolygon('PGND') Or  IsNamedPolygon('PGND') Or  IsNamedPolygon('Vbulk') Or  IsNamedPolygon('D106_1') Or  IsNamedPolygon('Vbulk') Or  IsNamedPolygon('D106_1') Or  IsNamedPolygon('VBB') Or  IsNamedPolygon('PGND') Or  IsNamedPolygon('PGND') Or  IsNamedPolygon('Vbulk') Or  IsNamedPolygon('VBB') Or  IsNamedPolygon('ZCD') Or  IsNamedPolygon('Vbulk') Or  IsNamedPolygon('ZCD') Or  IsNamedPolygon('VBB') Or  IsNamedPolygon('VBB') Or  IsNamedPolygon('VBB') Or  IsNamedPolygon('VBB') Or  IsNamedPolygon('VBB') Or  IsNamedPolygon('ZCD') Or  IsNamedPolygon('C102_1') Or  IsNamedPolygon('12Vp') Or  IsNamedPolygon('C105_1') Or  IsNamedPolygon('PGND') Or  IsNamedPolygon('SWNODE') Or  IsNamedPolygon('Vbulk') Or  IsNamedPolygon('Vbulk1') Or  IsNamedPolygon('Vbulk1') Or  IsNamedPolygon('Neutral') Or  IsNamedPolygon('ZCD') Or  IsNamedPolygon('Neutral') Or  IsNamedPolygon('ZCD') Or  IsNamedPolygon('5Vp') Or  IsNamedPolygon('Neutral') Or  IsNamedPolygon('ZCD') Or  IsNamedPolygon('Line') Or  IsNamedPolygon('ZCD')] p5: connectstyle=Direct reliefconductorwidth=10 reliefentries=4 polygonreliefangle="90 Angle" airgapwidth=10
PolygonConnect PolygonConnect_54 [All vs IsNamedPolygon('12Vp') Or  IsNamedPolygon('SWNODE') Or  IsNamedPolygon('D403_2') Or  IsNamedPolygon('D403_2') Or  IsNamedPolygon('PGND') Or  IsNamedPolygon('BOTTOM_LAYER_NETC106_2_P030') Or  IsNamedPolygon('C102_1') Or  IsNamedPolygon('SGND') Or  IsNamedPolygon('TOP_LAYER_54V1_P046') Or  IsNamedPolygon('TOP_LAYER_54V2_P048') Or  IsNamedPolygon('TOP_LAYER_54V2_P048') Or  IsNamedPolygon('C108_1') Or  IsNamedPolygon('C108_1') Or  IsNamedPolygon('C108_1') Or  IsNamedPolygon('C108_1') Or  IsNamedPolygon('C108_1') Or  IsNamedPolygon('C108_1') Or  IsNamedPolygon('PGND') Or  IsNamedPolygon('ZCD') Or  IsNamedPolygon('Line') Or  IsNamedPolygon('5Vp') Or  IsNamedPolygon('12Vp') Or  IsNamedPolygon('T200_4') Or  IsNamedPolygon('T200_6') Or  IsNamedPolygon('SWNODE3') Or  IsNamedPolygon('T200_4') Or  IsNamedPolygon('T200_6') Or  IsNamedPolygon('SWNODE4') Or  IsNamedPolygon('VSR') Or  IsNamedPolygon('TOP_LAYER_IOUT_SNS_P092') Or  IsNamedPolygon('SIGNAL_LAYER_2_VBB_P094') Or  IsNamedPolygon('Vbulk1') Or  IsNamedPolygon('TOP_LAYER_VBULK_P104') Or  IsNamedPolygon('SIGNAL_LAYER_1_VBULK1_P106') Or  IsNamedPolygon('Line') Or  IsNamedPolygon('Line') Or  IsNamedPolygon('D404_2') Or  IsNamedPolygon('Vbulk') Or  IsNamedPolygon('D400_2') Or  IsNamedPolygon('SGND') Or  IsNamedPolygon('PGND') Or  IsNamedPolygon('TOP_LAYER_12VS_P126') Or  IsNamedPolygon('LEG3_HS_DRV') Or  IsNamedPolygon('LEG4_LS_DRV') Or  IsNamedPolygon('LEG4_HS_DRV') Or  IsNamedPolygon('SWNODE4') Or  IsNamedPolygon('SWNODE3') Or  IsNamedPolygon('T200_6') Or  IsNamedPolygon('T200_4') Or  IsNamedPolygon('VBB') Or  IsNamedPolygon('5Vs') Or  IsNamedPolygon('SGND') Or  IsNamedPolygon('Iout_SNS') Or  IsNamedPolygon('SGND') Or  IsNamedPolygon('SWNODE3') Or  IsNamedPolygon('SWNODE3') Or  IsNamedPolygon('SWNODE3') Or  IsNamedPolygon('SWNODE3') Or  IsNamedPolygon('SGND') Or  IsNamedPolygon('SGND') Or  IsNamedPolygon('SGND') Or  IsNamedPolygon('SWNODE4') Or  IsNamedPolygon('SWNODE4') Or  IsNamedPolygon('SWNODE4') Or  IsNamedPolygon('VSR') Or  IsNamedPolygon('SWNODE3') Or  IsNamedPolygon('SGND') Or  IsNamedPolygon('SGND') Or  IsNamedPolygon('SGND') Or  IsNamedPolygon('SGND') Or  IsNamedPolygon('SGND') Or  IsNamedPolygon('SGND') Or  IsNamedPolygon('54V1') Or  IsNamedPolygon('SGND') Or  IsNamedPolygon('VSR') Or  IsNamedPolygon('C102_1') Or  IsNamedPolygon('C102_1') Or  IsNamedPolygon('C102_1') Or  IsNamedPolygon('C102_1') Or  IsNamedPolygon('C102_1') Or  IsNamedPolygon('ZCD') Or  IsNamedPolygon('PGND') Or  IsNamedPolygon('PGND') Or  IsNamedPolygon('Vbulk1') Or  IsNamedPolygon('Vbulk') Or  IsNamedPolygon('Vbulk1') Or  IsNamedPolygon('Vbulk1') Or  IsNamedPolygon('ZCD') Or  IsNamedPolygon('Neutral') Or  IsNamedPolygon('Neutral') Or  IsNamedPolygon('C106_2') Or  IsNamedPolygon('C106_2') Or  IsNamedPolygon('C106_2') Or  IsNamedPolygon('SWNODE') Or  IsNamedPolygon('Vbulk1') Or  IsNamedPolygon('Earth1') Or  IsNamedPolygon('Earth1') Or  IsNamedPolygon('Earth1') Or  IsNamedPolygon('Earth1') Or  IsNamedPolygon('Earth1') Or  IsNamedPolygon('Earth1') Or  IsNamedPolygon('ZCD') Or  IsNamedPolygon('VBB') Or  IsNamedPolygon('PGND') Or  IsNamedPolygon('D106_1') Or  IsNamedPolygon('PGND') Or  IsNamedPolygon('PGND') Or  IsNamedPolygon('D106_1') Or  IsNamedPolygon('Vbulk') Or  IsNamedPolygon('D106_1') Or  IsNamedPolygon('PGND') Or  IsNamedPolygon('VBB') Or  IsNamedPolygon('VBB') Or  IsNamedPolygon('PGND') Or  IsNamedPolygon('PGND') Or  IsNamedPolygon('PGND') Or  IsNamedPolygon('PGND') Or  IsNamedPolygon('PGND') Or  IsNamedPolygon('ZCD') Or  IsNamedPolygon('ZCD') Or  IsNamedPolygon('C412_2') Or  IsNamedPolygon('VBB') Or  IsNamedPolygon('PGND') Or  IsNamedPolygon('PGND') Or  IsNamedPolygon('PGND') Or  IsNamedPolygon('PGND') Or  IsNamedPolygon('PGND') Or  IsNamedPolygon('PGND') Or  IsNamedPolygon('PGND') Or  IsNamedPolygon('Vbulk') Or  IsNamedPolygon('D404_2') Or  IsNamedPolygon('PGND') Or  IsNamedPolygon('Iout_SNS') Or  IsNamedPolygon('54V2') Or  IsNamedPolygon('54V2') Or  IsNamedPolygon('54V2') Or  IsNamedPolygon('54V2') Or  IsNamedPolygon('VSR') Or  IsNamedPolygon('VSR') Or  IsNamedPolygon('Iout_SNS') Or  IsNamedPolygon('SGND') Or  IsNamedPolygon('SGND') Or  IsNamedPolygon('BOTTOM_LAYER_54V1_P154') Or  IsNamedPolygon('ZCD') Or  IsNamedPolygon('PGND')] p6: connectstyle=Direct reliefconductorwidth=10 reliefentries=4 polygonreliefangle="90 Angle" airgapwidth=10
PolygonConnect PolygonConnect_53 [All vs IsNamedPolygon('BOTTOM_LAYER_54V1_P350')] p7: connectstyle=Direct reliefconductorwidth=10 reliefentries=4 polygonreliefangle="90 Angle" airgapwidth=10
PolygonConnect PolygonConnect_52 [All vs IsNamedPolygon('TOP_LAYER_54V1_P046')] p8: connectstyle=Direct reliefconductorwidth=10 reliefentries=4 polygonreliefangle="90 Angle" airgapwidth=10
PolygonConnect PolygonConnect_51 [All vs IsNamedPolygon('SIGNAL_LAYER_1_VBULK1_P106')] p9: connectstyle=Direct reliefconductorwidth=10 reliefentries=4 polygonreliefangle="90 Angle" airgapwidth=10
PolygonConnect PolygonConnect_50 [All vs IsNamedPolygon('BOTTOM_LAYER_54V1_P128')] p10: connectstyle=Direct reliefconductorwidth=10 reliefentries=4 polygonreliefangle="90 Angle" airgapwidth=10
PolygonConnect PolygonConnect_49 [All vs IsNamedPolygon('BOTTOM_LAYER_54V1_P128')] p11: connectstyle=Direct reliefconductorwidth=10 reliefentries=4 polygonreliefangle="90 Angle" airgapwidth=10
PolygonConnect PolygonConnect_48 [All vs IsNamedPolygon('BOTTOM_LAYER_54V1_P128')] p12: connectstyle=Direct reliefconductorwidth=10 reliefentries=4 polygonreliefangle="90 Angle" airgapwidth=10
PolygonConnect PolygonConnect_47 [All vs IsNamedPolygon('BOTTOM_LAYER_54V1_P128')] p13: connectstyle=Direct reliefconductorwidth=10 reliefentries=4 polygonreliefangle="90 Angle" airgapwidth=10
PolygonConnect PolygonConnect_46 [All vs IsNamedPolygon('PGND') Or  IsNamedPolygon('T200_4') Or  IsNamedPolygon('VBB') Or  IsNamedPolygon('SWNODE3') Or  IsNamedPolygon('LEG4_LS_DRV') Or  IsNamedPolygon('Iout_SNS') Or  IsNamedPolygon('SWNODE3') Or  IsNamedPolygon('T200_6') Or  IsNamedPolygon('SGND') Or  IsNamedPolygon('SIGNAL_LAYER_1_VBULK1_P106') Or  IsNamedPolygon('LEG3_HS_DRV') Or  IsNamedPolygon('TOP_LAYER_12VS_P126') Or  IsNamedPolygon('LEG4_HS_DRV') Or  IsNamedPolygon('SWNODE3') Or  IsNamedPolygon('SGND') Or  IsNamedPolygon('BOTTOM_LAYER_54V1_P128') Or  IsNamedPolygon('SGND') Or  IsNamedPolygon('Line') Or  IsNamedPolygon('TOP_LAYER_IOUT_SNS_P092') Or  IsNamedPolygon('C108_1') Or  IsNamedPolygon('D403_2') Or  IsNamedPolygon('SWNODE') Or  IsNamedPolygon('SIGNAL_LAYER_2_VBB_P094') Or  IsNamedPolygon('Vbulk') Or  IsNamedPolygon('D404_2') Or  IsNamedPolygon('VSR') Or  IsNamedPolygon('C108_1') Or  IsNamedPolygon('C108_1') Or  IsNamedPolygon('5Vp') Or  IsNamedPolygon('C108_1') Or  IsNamedPolygon('PGND') Or  IsNamedPolygon('D400_2') Or  IsNamedPolygon('SWNODE3') Or  IsNamedPolygon('Line') Or  IsNamedPolygon('C108_1') Or  IsNamedPolygon('TOP_LAYER_VBULK_P104') Or  IsNamedPolygon('Vbulk1') Or  IsNamedPolygon('T200_6') Or  IsNamedPolygon('T200_6') Or  IsNamedPolygon('SWNODE4') Or  IsNamedPolygon('C108_1') Or  IsNamedPolygon('D403_2') Or  IsNamedPolygon('PGND') Or  IsNamedPolygon('T200_4') Or  IsNamedPolygon('Line') Or  IsNamedPolygon('5Vs') Or  IsNamedPolygon('12Vp') Or  IsNamedPolygon('C102_1') Or  IsNamedPolygon('SGND') Or  IsNamedPolygon('TOP_LAYER_54V2_P048') Or  IsNamedPolygon('TOP_LAYER_54V1_P046') Or  IsNamedPolygon('SWNODE4') Or  IsNamedPolygon('ZCD') Or  IsNamedPolygon('SWNODE3') Or  IsNamedPolygon('SWNODE3') Or  IsNamedPolygon('BOTTOM_LAYER_NETC106_2_P030') Or  IsNamedPolygon('TOP_LAYER_54V2_P048') Or  IsNamedPolygon('T200_4') Or  IsNamedPolygon('SWNODE4') Or  IsNamedPolygon('SWNODE4') Or  IsNamedPolygon('SGND') Or  IsNamedPolygon('SGND') Or  IsNamedPolygon('SGND') Or  IsNamedPolygon('SWNODE4') Or  IsNamedPolygon('VSR') Or  IsNamedPolygon('SWNODE3') Or  IsNamedPolygon('SGND') Or  IsNamedPolygon('SGND') Or  IsNamedPolygon('SGND') Or  IsNamedPolygon('SGND') Or  IsNamedPolygon('SGND') Or  IsNamedPolygon('SGND') Or  IsNamedPolygon('BOTTOM_LAYER_54V1_P128') Or  IsNamedPolygon('SGND') Or  IsNamedPolygon('VSR') Or  IsNamedPolygon('C102_1') Or  IsNamedPolygon('C102_1') Or  IsNamedPolygon('C102_1') Or  IsNamedPolygon('C102_1') Or  IsNamedPolygon('C102_1') Or  IsNamedPolygon('ZCD') Or  IsNamedPolygon('PGND') Or  IsNamedPolygon('PGND') Or  IsNamedPolygon('Vbulk1') Or  IsNamedPolygon('Vbulk') Or  IsNamedPolygon('Vbulk1') Or  IsNamedPolygon('Vbulk1') Or  IsNamedPolygon('ZCD') Or  IsNamedPolygon('Neutral') Or  IsNamedPolygon('Neutral') Or  IsNamedPolygon('C106_2') Or  IsNamedPolygon('C106_2') Or  IsNamedPolygon('C106_2') Or  IsNamedPolygon('SWNODE') Or  IsNamedPolygon('Vbulk1') Or  IsNamedPolygon('Earth1') Or  IsNamedPolygon('Earth1') Or  IsNamedPolygon('Earth1') Or  IsNamedPolygon('Earth1') Or  IsNamedPolygon('Earth1') Or  IsNamedPolygon('Earth1') Or  IsNamedPolygon('ZCD') Or  IsNamedPolygon('VBB') Or  IsNamedPolygon('PGND') Or  IsNamedPolygon('D106_1') Or  IsNamedPolygon('PGND') Or  IsNamedPolygon('PGND') Or  IsNamedPolygon('D106_1') Or  IsNamedPolygon('Vbulk') Or  IsNamedPolygon('D106_1') Or  IsNamedPolygon('PGND') Or  IsNamedPolygon('VBB') Or  IsNamedPolygon('VBB') Or  IsNamedPolygon('PGND') Or  IsNamedPolygon('PGND') Or  IsNamedPolygon('PGND') Or  IsNamedPolygon('PGND') Or  IsNamedPolygon('PGND') Or  IsNamedPolygon('ZCD') Or  IsNamedPolygon('ZCD') Or  IsNamedPolygon('C412_2') Or  IsNamedPolygon('VBB') Or  IsNamedPolygon('PGND') Or  IsNamedPolygon('PGND') Or  IsNamedPolygon('PGND') Or  IsNamedPolygon('PGND') Or  IsNamedPolygon('PGND') Or  IsNamedPolygon('PGND') Or  IsNamedPolygon('PGND') Or  IsNamedPolygon('Vbulk') Or  IsNamedPolygon('D404_2') Or  IsNamedPolygon('PGND') Or  IsNamedPolygon('Iout_SNS') Or  IsNamedPolygon('54V2')] p14: connectstyle=Direct reliefconductorwidth=10 reliefentries=4 polygonreliefangle="90 Angle" airgapwidth=10
PolygonConnect PolygonConnect_45 [All vs IsNamedPolygon('Vbulk1') Or  IsNamedPolygon('TOP_LAYER_VBULK_P104') Or  IsNamedPolygon('SIGNAL_LAYER_1_VBULK1_P106') Or  IsNamedPolygon('Iout_SNS') Or  IsNamedPolygon('SIGNAL_LAYER_2_VBB_P094') Or  IsNamedPolygon('Line') Or  IsNamedPolygon('T200_4') Or  IsNamedPolygon('ZCD') Or  IsNamedPolygon('C108_1') Or  IsNamedPolygon('PGND') Or  IsNamedPolygon('BOTTOM_LAYER_NETC106_2_P030') Or  IsNamedPolygon('5Vp') Or  IsNamedPolygon('C108_1') Or  IsNamedPolygon('Line') Or  IsNamedPolygon('C102_1') Or  IsNamedPolygon('T200_4') Or  IsNamedPolygon('12Vp') Or  IsNamedPolygon('D403_2') Or  IsNamedPolygon('T200_6') Or  IsNamedPolygon('TOP_LAYER_54V1_P046') Or  IsNamedPolygon('TOP_LAYER_54V2_P048') Or  IsNamedPolygon('C108_1') Or  IsNamedPolygon('C108_1') Or  IsNamedPolygon('SWNODE3') Or  IsNamedPolygon('TOP_LAYER_54V2_P048') Or  IsNamedPolygon('PGND') Or  IsNamedPolygon('D403_2') Or  IsNamedPolygon('C108_1') Or  IsNamedPolygon('C108_1') Or  IsNamedPolygon('T200_6') Or  IsNamedPolygon('SGND') Or  IsNamedPolygon('SWNODE') Or  IsNamedPolygon('SGND') Or  IsNamedPolygon('SWNODE3') Or  IsNamedPolygon('BOTTOM_LAYER_54V1_P128') Or  IsNamedPolygon('C102_1') Or  IsNamedPolygon('SWNODE4') Or  IsNamedPolygon('C102_1') Or  IsNamedPolygon('SGND') Or  IsNamedPolygon('C102_1') Or  IsNamedPolygon('SGND') Or  IsNamedPolygon('VSR') Or  IsNamedPolygon('SGND') Or  IsNamedPolygon('SGND') Or  IsNamedPolygon('VSR') Or  IsNamedPolygon('SGND') Or  IsNamedPolygon('SWNODE4') Or  IsNamedPolygon('SGND') Or  IsNamedPolygon('SGND') Or  IsNamedPolygon('Vbulk1') Or  IsNamedPolygon('SGND') Or  IsNamedPolygon('PGND') Or  IsNamedPolygon('SGND') Or  IsNamedPolygon('PGND') Or  IsNamedPolygon('SWNODE3') Or  IsNamedPolygon('ZCD') Or  IsNamedPolygon('VSR') Or  IsNamedPolygon('C102_1') Or  IsNamedPolygon('SWNODE4') Or  IsNamedPolygon('C102_1') Or  IsNamedPolygon('SWNODE4') Or  IsNamedPolygon('SWNODE3') Or  IsNamedPolygon('PGND') Or  IsNamedPolygon('SGND') Or  IsNamedPolygon('D400_2') Or  IsNamedPolygon('SGND') Or  IsNamedPolygon('5Vs') Or  IsNamedPolygon('VBB') Or  IsNamedPolygon('T200_4') Or  IsNamedPolygon('T200_6') Or  IsNamedPolygon('SWNODE4') Or  IsNamedPolygon('LEG4_HS_DRV') Or  IsNamedPolygon('LEG4_LS_DRV') Or  IsNamedPolygon('LEG3_HS_DRV') Or  IsNamedPolygon('BOTTOM_LAYER_54V1_P128') Or  IsNamedPolygon('TOP_LAYER_12VS_P126') Or  IsNamedPolygon('Iout_SNS') Or  IsNamedPolygon('SWNODE3') Or  IsNamedPolygon('SWNODE3') Or  IsNamedPolygon('SWNODE3') Or  IsNamedPolygon('VBB') Or  IsNamedPolygon('Line') Or  IsNamedPolygon('D404_2') Or  IsNamedPolygon('SGND') Or  IsNamedPolygon('VBB') Or  IsNamedPolygon('VBB') Or  IsNamedPolygon('PGND') Or  IsNamedPolygon('PGND') Or  IsNamedPolygon('PGND') Or  IsNamedPolygon('PGND') Or  IsNamedPolygon('PGND') Or  IsNamedPolygon('ZCD') Or  IsNamedPolygon('ZCD') Or  IsNamedPolygon('C412_2') Or  IsNamedPolygon('VBB') Or  IsNamedPolygon('PGND') Or  IsNamedPolygon('PGND') Or  IsNamedPolygon('PGND') Or  IsNamedPolygon('PGND') Or  IsNamedPolygon('PGND') Or  IsNamedPolygon('PGND') Or  IsNamedPolygon('PGND') Or  IsNamedPolygon('VBB') Or  IsNamedPolygon('D404_2') Or  IsNamedPolygon('VBB') Or  IsNamedPolygon('Vbulk1') Or  IsNamedPolygon('Vbulk1') Or  IsNamedPolygon('ZCD') Or  IsNamedPolygon('Neutral') Or  IsNamedPolygon('Neutral') Or  IsNamedPolygon('C106_2') Or  IsNamedPolygon('C106_2') Or  IsNamedPolygon('C106_2') Or  IsNamedPolygon('SWNODE') Or  IsNamedPolygon('Vbulk1') Or  IsNamedPolygon('Earth1') Or  IsNamedPolygon('Earth1') Or  IsNamedPolygon('Earth1') Or  IsNamedPolygon('Earth1') Or  IsNamedPolygon('Earth1') Or  IsNamedPolygon('Earth1') Or  IsNamedPolygon('ZCD') Or  IsNamedPolygon('VBB') Or  IsNamedPolygon('PGND') Or  IsNamedPolygon('D106_1') Or  IsNamedPolygon('PGND') Or  IsNamedPolygon('PGND') Or  IsNamedPolygon('D106_1') Or  IsNamedPolygon('VBB') Or  IsNamedPolygon('D106_1') Or  IsNamedPolygon('PGND')] p15: connectstyle=Direct reliefconductorwidth=10 reliefentries=4 polygonreliefangle="90 Angle" airgapwidth=10
PolygonConnect PolygonConnect_44 [All vs IsNamedPolygon('Earth1') Or  IsNamedPolygon('Vbulk1') Or  IsNamedPolygon('Vbulk1') Or  IsNamedPolygon('VBB') Or  IsNamedPolygon('Vbulk1') Or  IsNamedPolygon('ZCD') Or  IsNamedPolygon('VBB') Or  IsNamedPolygon('PGND') Or  IsNamedPolygon('C412_2') Or  IsNamedPolygon('ZCD') Or  IsNamedPolygon('D106_1') Or  IsNamedPolygon('D106_1') Or  IsNamedPolygon('ZCD') Or  IsNamedPolygon('PGND') Or  IsNamedPolygon('PGND') Or  IsNamedPolygon('ZCD') Or  IsNamedPolygon('VBB') Or  IsNamedPolygon('PGND') Or  IsNamedPolygon('VBB') Or  IsNamedPolygon('PGND') Or  IsNamedPolygon('D106_1') Or  IsNamedPolygon('PGND') Or  IsNamedPolygon('PGND') Or  IsNamedPolygon('PGND') Or  IsNamedPolygon('VBB') Or  IsNamedPolygon('PGND') Or  IsNamedPolygon('PGND') Or  IsNamedPolygon('C102_1') Or  IsNamedPolygon('ZCD') Or  IsNamedPolygon('C102_1') Or  IsNamedPolygon('C102_1') Or  IsNamedPolygon('C102_1') Or  IsNamedPolygon('PGND') Or  IsNamedPolygon('C102_1') Or  IsNamedPolygon('Line') Or  IsNamedPolygon('T200_4') Or  IsNamedPolygon('T200_4') Or  IsNamedPolygon('SIGNAL_LAYER_1_VBULK1_P106') Or  IsNamedPolygon('TOP_LAYER_VBULK_P104') Or  IsNamedPolygon('T200_4') Or  IsNamedPolygon('SGND') Or  IsNamedPolygon('T200_6') Or  IsNamedPolygon('C108_1') Or  IsNamedPolygon('SWNODE3') Or  IsNamedPolygon('SWNODE') Or  IsNamedPolygon('SWNODE3') Or  IsNamedPolygon('LEG3_HS_DRV') Or  IsNamedPolygon('BOTTOM_LAYER_NETC106_2_P030') Or  IsNamedPolygon('C102_1') Or  IsNamedPolygon('SWNODE4') Or  IsNamedPolygon('SIGNAL_LAYER_2_VBB_P094') Or  IsNamedPolygon('SGND') Or  IsNamedPolygon('VSR') Or  IsNamedPolygon('C108_1') Or  IsNamedPolygon('BOTTOM_LAYER_54V1_P128') Or  IsNamedPolygon('TOP_LAYER_54V2_P048') Or  IsNamedPolygon('TOP_LAYER_54V1_P046') Or  IsNamedPolygon('C108_1') Or  IsNamedPolygon('D403_2') Or  IsNamedPolygon('ZCD') Or  IsNamedPolygon('PGND') Or  IsNamedPolygon('SWNODE3') Or  IsNamedPolygon('Line') Or  IsNamedPolygon('D400_2') Or  IsNamedPolygon('SGND') Or  IsNamedPolygon('PGND') Or  IsNamedPolygon('SGND') Or  IsNamedPolygon('LEG4_HS_DRV') Or  IsNamedPolygon('SWNODE3') Or  IsNamedPolygon('5Vs') Or  IsNamedPolygon('SWNODE4') Or  IsNamedPolygon('SGND') Or  IsNamedPolygon('SGND') Or  IsNamedPolygon('C108_1') Or  IsNamedPolygon('5Vp') Or  IsNamedPolygon('12Vp') Or  IsNamedPolygon('Iout_SNS') Or  IsNamedPolygon('D404_2') Or  IsNamedPolygon('SGND') Or  IsNamedPolygon('T200_6') Or  IsNamedPolygon('TOP_LAYER_54V2_P048') Or  IsNamedPolygon('SGND') Or  IsNamedPolygon('SWNODE3') Or  IsNamedPolygon('SWNODE4') Or  IsNamedPolygon('Iout_SNS') Or  IsNamedPolygon('C108_1') Or  IsNamedPolygon('BOTTOM_LAYER_54V1_P128') Or  IsNamedPolygon('SWNODE3') Or  IsNamedPolygon('LEG4_LS_DRV') Or  IsNamedPolygon('SGND') Or  IsNamedPolygon('SWNODE4') Or  IsNamedPolygon('T200_6') Or  IsNamedPolygon('TOP_LAYER_12VS_P126') Or  IsNamedPolygon('Line') Or  IsNamedPolygon('Vbulk1') Or  IsNamedPolygon('SWNODE3') Or  IsNamedPolygon('SGND') Or  IsNamedPolygon('VBB') Or  IsNamedPolygon('SGND') Or  IsNamedPolygon('SGND') Or  IsNamedPolygon('SWNODE4') Or  IsNamedPolygon('PGND') Or  IsNamedPolygon('D403_2') Or  IsNamedPolygon('VSR') Or  IsNamedPolygon('SGND') Or  IsNamedPolygon('SGND') Or  IsNamedPolygon('VBB') Or  IsNamedPolygon('C108_1') Or  IsNamedPolygon('Earth1') Or  IsNamedPolygon('Earth1') Or  IsNamedPolygon('VSR') Or  IsNamedPolygon('C106_2') Or  IsNamedPolygon('Vbulk1') Or  IsNamedPolygon('C106_2') Or  IsNamedPolygon('C106_2') Or  IsNamedPolygon('Earth1') Or  IsNamedPolygon('SWNODE') Or  IsNamedPolygon('Neutral') Or  IsNamedPolygon('Earth1') Or  IsNamedPolygon('Earth1') Or  IsNamedPolygon('Neutral')] p16: connectstyle=Direct reliefconductorwidth=10 reliefentries=4 polygonreliefangle="90 Angle" airgapwidth=10
PolygonConnect PolygonConnect_43 [All vs IsNamedPolygon('SWNODE') Or  IsNamedPolygon('D403_2') Or  IsNamedPolygon('D403_2') Or  IsNamedPolygon('PGND') Or  IsNamedPolygon('BOTTOM_LAYER_NETC106_2_P030') Or  IsNamedPolygon('C102_1') Or  IsNamedPolygon('SGND') Or  IsNamedPolygon('TOP_LAYER_54V1_P046') Or  IsNamedPolygon('TOP_LAYER_54V2_P048') Or  IsNamedPolygon('TOP_LAYER_54V2_P048') Or  IsNamedPolygon('C108_1') Or  IsNamedPolygon('C108_1') Or  IsNamedPolygon('C108_1') Or  IsNamedPolygon('C108_1') Or  IsNamedPolygon('C108_1') Or  IsNamedPolygon('C108_1') Or  IsNamedPolygon('PGND') Or  IsNamedPolygon('ZCD') Or  IsNamedPolygon('Line') Or  IsNamedPolygon('5Vp') Or  IsNamedPolygon('12Vp') Or  IsNamedPolygon('T200_4') Or  IsNamedPolygon('T200_6') Or  IsNamedPolygon('SWNODE3') Or  IsNamedPolygon('T200_4') Or  IsNamedPolygon('T200_6') Or  IsNamedPolygon('SWNODE4') Or  IsNamedPolygon('VSR') Or  IsNamedPolygon('Iout_SNS') Or  IsNamedPolygon('SIGNAL_LAYER_2_VBB_P094') Or  IsNamedPolygon('Vbulk1') Or  IsNamedPolygon('TOP_LAYER_VBULK_P104') Or  IsNamedPolygon('SIGNAL_LAYER_1_VBULK1_P106') Or  IsNamedPolygon('Line') Or  IsNamedPolygon('Line') Or  IsNamedPolygon('D404_2') Or  IsNamedPolygon('VBB') Or  IsNamedPolygon('D400_2') Or  IsNamedPolygon('SGND') Or  IsNamedPolygon('PGND') Or  IsNamedPolygon('TOP_LAYER_12VS_P126') Or  IsNamedPolygon('BOTTOM_LAYER_54V1_P128') Or  IsNamedPolygon('LEG3_HS_DRV') Or  IsNamedPolygon('LEG4_LS_DRV') Or  IsNamedPolygon('LEG4_HS_DRV') Or  IsNamedPolygon('SWNODE4') Or  IsNamedPolygon('SWNODE3') Or  IsNamedPolygon('T200_6') Or  IsNamedPolygon('T200_4') Or  IsNamedPolygon('VBB') Or  IsNamedPolygon('5Vs') Or  IsNamedPolygon('SGND') Or  IsNamedPolygon('Iout_SNS') Or  IsNamedPolygon('SGND') Or  IsNamedPolygon('SWNODE3') Or  IsNamedPolygon('SWNODE3') Or  IsNamedPolygon('SWNODE3') Or  IsNamedPolygon('SWNODE3') Or  IsNamedPolygon('SGND') Or  IsNamedPolygon('SGND') Or  IsNamedPolygon('SGND') Or  IsNamedPolygon('SWNODE4') Or  IsNamedPolygon('SWNODE4') Or  IsNamedPolygon('SWNODE4') Or  IsNamedPolygon('VSR') Or  IsNamedPolygon('SWNODE3') Or  IsNamedPolygon('SGND') Or  IsNamedPolygon('SGND') Or  IsNamedPolygon('SGND') Or  IsNamedPolygon('SGND') Or  IsNamedPolygon('SGND') Or  IsNamedPolygon('SGND') Or  IsNamedPolygon('BOTTOM_LAYER_54V1_P128') Or  IsNamedPolygon('SGND') Or  IsNamedPolygon('VSR') Or  IsNamedPolygon('C102_1') Or  IsNamedPolygon('C102_1') Or  IsNamedPolygon('C102_1') Or  IsNamedPolygon('C102_1') Or  IsNamedPolygon('C102_1') Or  IsNamedPolygon('ZCD') Or  IsNamedPolygon('PGND') Or  IsNamedPolygon('PGND') Or  IsNamedPolygon('Vbulk1') Or  IsNamedPolygon('VBB') Or  IsNamedPolygon('Vbulk1') Or  IsNamedPolygon('Vbulk1') Or  IsNamedPolygon('ZCD') Or  IsNamedPolygon('Neutral') Or  IsNamedPolygon('Neutral') Or  IsNamedPolygon('C106_2') Or  IsNamedPolygon('C106_2') Or  IsNamedPolygon('C106_2') Or  IsNamedPolygon('SWNODE') Or  IsNamedPolygon('Vbulk1') Or  IsNamedPolygon('Earth1') Or  IsNamedPolygon('Earth1') Or  IsNamedPolygon('Earth1') Or  IsNamedPolygon('Earth1') Or  IsNamedPolygon('Earth1') Or  IsNamedPolygon('Earth1') Or  IsNamedPolygon('ZCD') Or  IsNamedPolygon('VBB') Or  IsNamedPolygon('PGND') Or  IsNamedPolygon('D106_1') Or  IsNamedPolygon('PGND') Or  IsNamedPolygon('PGND') Or  IsNamedPolygon('D106_1') Or  IsNamedPolygon('VBB') Or  IsNamedPolygon('D106_1') Or  IsNamedPolygon('PGND') Or  IsNamedPolygon('VBB') Or  IsNamedPolygon('VBB') Or  IsNamedPolygon('PGND') Or  IsNamedPolygon('PGND') Or  IsNamedPolygon('PGND') Or  IsNamedPolygon('PGND') Or  IsNamedPolygon('PGND')] p17: connectstyle=Direct reliefconductorwidth=10 reliefentries=4 polygonreliefangle="90 Angle" airgapwidth=10
PolygonConnect PolygonConnect_42 [All vs IsNamedPolygon('Neutral') Or  IsNamedPolygon('Earth1') Or  IsNamedPolygon('Earth1') Or  IsNamedPolygon('D404_2') Or  IsNamedPolygon('Line') Or  IsNamedPolygon('SIGNAL_LAYER_1_VBULK1_P106') Or  IsNamedPolygon('Line') Or  IsNamedPolygon('C102_1') Or  IsNamedPolygon('SWNODE3') Or  IsNamedPolygon('SWNODE3') Or  IsNamedPolygon('SWNODE') Or  IsNamedPolygon('5Vp') Or  IsNamedPolygon('T200_6') Or  IsNamedPolygon('SWNODE3') Or  IsNamedPolygon('SGND') Or  IsNamedPolygon('SWNODE3') Or  IsNamedPolygon('VSR') Or  IsNamedPolygon('C108_1') Or  IsNamedPolygon('SWNODE3') Or  IsNamedPolygon('TOP_LAYER_12VS_P126') Or  IsNamedPolygon('SGND') Or  IsNamedPolygon('SGND') Or  IsNamedPolygon('SGND') Or  IsNamedPolygon('T200_6') Or  IsNamedPolygon('SWNODE4') Or  IsNamedPolygon('C108_1') Or  IsNamedPolygon('C106_2') Or  IsNamedPolygon('SGND') Or  IsNamedPolygon('Neutral') Or  IsNamedPolygon('SIGNAL_LAYER_2_VBB_P094') Or  IsNamedPolygon('Vbulk1') Or  IsNamedPolygon('SGND') Or  IsNamedPolygon('SGND') Or  IsNamedPolygon('TOP_LAYER_54V1_P046') Or  IsNamedPolygon('TOP_LAYER_54V2_P048') Or  IsNamedPolygon('TOP_LAYER_54V2_P048') Or  IsNamedPolygon('C102_1') Or  IsNamedPolygon('SGND') Or  IsNamedPolygon('T200_4') Or  IsNamedPolygon('12Vp') Or  IsNamedPolygon('SGND') Or  IsNamedPolygon('D400_2') Or  IsNamedPolygon('LEG3_HS_DRV') Or  IsNamedPolygon('LEG4_LS_DRV') Or  IsNamedPolygon('T200_4') Or  IsNamedPolygon('BOTTOM_LAYER_54V1_P128') Or  IsNamedPolygon('SGND') Or  IsNamedPolygon('VBB') Or  IsNamedPolygon('SWNODE4') Or  IsNamedPolygon('SWNODE4') Or  IsNamedPolygon('SWNODE4') Or  IsNamedPolygon('VSR') Or  IsNamedPolygon('Iout_SNS') Or  IsNamedPolygon('VBB') Or  IsNamedPolygon('PGND') Or  IsNamedPolygon('Line') Or  IsNamedPolygon('ZCD') Or  IsNamedPolygon('D403_2') Or  IsNamedPolygon('SWNODE3') Or  IsNamedPolygon('Vbulk1') Or  IsNamedPolygon('ZCD') Or  IsNamedPolygon('LEG4_HS_DRV') Or  IsNamedPolygon('BOTTOM_LAYER_54V1_P128') Or  IsNamedPolygon('VBB') Or  IsNamedPolygon('PGND') Or  IsNamedPolygon('ZCD') Or  IsNamedPolygon('ZCD') Or  IsNamedPolygon('Earth1') Or  IsNamedPolygon('VBB') Or  IsNamedPolygon('PGND') Or  IsNamedPolygon('PGND') Or  IsNamedPolygon('Vbulk1') Or  IsNamedPolygon('SWNODE') Or  IsNamedPolygon('C106_2') Or  IsNamedPolygon('C106_2') Or  IsNamedPolygon('C108_1') Or  IsNamedPolygon('SWNODE3') Or  IsNamedPolygon('SWNODE4') Or  IsNamedPolygon('Vbulk1') Or  IsNamedPolygon('SGND') Or  IsNamedPolygon('C102_1') Or  IsNamedPolygon('BOTTOM_LAYER_NETC106_2_P030') Or  IsNamedPolygon('Earth1') Or  IsNamedPolygon('Earth1') Or  IsNamedPolygon('Vbulk1') Or  IsNamedPolygon('Earth1') Or  IsNamedPolygon('T200_6') Or  IsNamedPolygon('T200_4') Or  IsNamedPolygon('C102_1') Or  IsNamedPolygon('C102_1') Or  IsNamedPolygon('C102_1') Or  IsNamedPolygon('VBB') Or  IsNamedPolygon('5Vs') Or  IsNamedPolygon('SGND') Or  IsNamedPolygon('Iout_SNS') Or  IsNamedPolygon('C108_1') Or  IsNamedPolygon('C108_1') Or  IsNamedPolygon('C108_1') Or  IsNamedPolygon('PGND') Or  IsNamedPolygon('D403_2') Or  IsNamedPolygon('PGND') Or  IsNamedPolygon('SGND') Or  IsNamedPolygon('SGND') Or  IsNamedPolygon('VSR')] p18: connectstyle=Direct reliefconductorwidth=10 reliefentries=4 polygonreliefangle="90 Angle" airgapwidth=10
PolygonConnect PolygonConnect_41 [All vs IsNamedPolygon('VBB') Or  IsNamedPolygon('SWNODE3') Or  IsNamedPolygon('T200_4') Or  IsNamedPolygon('Earth1') Or  IsNamedPolygon('BOTTOM_LAYER_54V1_P128') Or  IsNamedPolygon('SGND') Or  IsNamedPolygon('TOP_LAYER_12VS_P126') Or  IsNamedPolygon('C102_1') Or  IsNamedPolygon('VSR') Or  IsNamedPolygon('Earth1') Or  IsNamedPolygon('Neutral') Or  IsNamedPolygon('Vbulk1') Or  IsNamedPolygon('SWNODE4') Or  IsNamedPolygon('C106_2') Or  IsNamedPolygon('PGND') Or  IsNamedPolygon('SGND') Or  IsNamedPolygon('VBB') Or  IsNamedPolygon('PGND') Or  IsNamedPolygon('LEG4_LS_DRV') Or  IsNamedPolygon('C102_1') Or  IsNamedPolygon('SWNODE4') Or  IsNamedPolygon('C106_2') Or  IsNamedPolygon('Vbulk1') Or  IsNamedPolygon('C102_1') Or  IsNamedPolygon('BOTTOM_LAYER_54V1_P128') Or  IsNamedPolygon('LEG3_HS_DRV') Or  IsNamedPolygon('SGND') Or  IsNamedPolygon('SGND') Or  IsNamedPolygon('Earth1') Or  IsNamedPolygon('SGND') Or  IsNamedPolygon('SGND') Or  IsNamedPolygon('5Vs') Or  IsNamedPolygon('LEG4_HS_DRV') Or  IsNamedPolygon('Earth1') Or  IsNamedPolygon('SGND') Or  IsNamedPolygon('SWNODE3') Or  IsNamedPolygon('Iout_SNS') Or  IsNamedPolygon('ZCD') Or  IsNamedPolygon('Earth1') Or  IsNamedPolygon('VSR') Or  IsNamedPolygon('C102_1') Or  IsNamedPolygon('C102_1') Or  IsNamedPolygon('Vbulk1') Or  IsNamedPolygon('C106_2') Or  IsNamedPolygon('ZCD') Or  IsNamedPolygon('SWNODE3') Or  IsNamedPolygon('SWNODE3') Or  IsNamedPolygon('Vbulk1') Or  IsNamedPolygon('SWNODE4') Or  IsNamedPolygon('Neutral') Or  IsNamedPolygon('SWNODE3') Or  IsNamedPolygon('SWNODE4') Or  IsNamedPolygon('Earth1') Or  IsNamedPolygon('D400_2') Or  IsNamedPolygon('SGND') Or  IsNamedPolygon('SGND') Or  IsNamedPolygon('SGND') Or  IsNamedPolygon('SWNODE') Or  IsNamedPolygon('VSR') Or  IsNamedPolygon('SGND') Or  IsNamedPolygon('SIGNAL_LAYER_1_VBULK1_P106') Or  IsNamedPolygon('SGND') Or  IsNamedPolygon('T200_6') Or  IsNamedPolygon('SWNODE4') Or  IsNamedPolygon('VBB') Or  IsNamedPolygon('T200_6') Or  IsNamedPolygon('Line') Or  IsNamedPolygon('Iout_SNS') Or  IsNamedPolygon('Vbulk1') Or  IsNamedPolygon('VBB') Or  IsNamedPolygon('SIGNAL_LAYER_2_VBB_P094') Or  IsNamedPolygon('SGND') Or  IsNamedPolygon('D404_2') Or  IsNamedPolygon('SWNODE3') Or  IsNamedPolygon('Line') Or  IsNamedPolygon('PGND') Or  IsNamedPolygon('TOP_LAYER_54V2_P048') Or  IsNamedPolygon('TOP_LAYER_54V1_P046') Or  IsNamedPolygon('TOP_LAYER_54V2_P048') Or  IsNamedPolygon('C108_1') Or  IsNamedPolygon('BOTTOM_LAYER_NETC106_2_P030') Or  IsNamedPolygon('D403_2') Or  IsNamedPolygon('T200_4') Or  IsNamedPolygon('Line') Or  IsNamedPolygon('PGND') Or  IsNamedPolygon('SWNODE3') Or  IsNamedPolygon('ZCD') Or  IsNamedPolygon('SWNODE') Or  IsNamedPolygon('D403_2') Or  IsNamedPolygon('C108_1') Or  IsNamedPolygon('C102_1') Or  IsNamedPolygon('C108_1') Or  IsNamedPolygon('PGND') Or  IsNamedPolygon('C108_1') Or  IsNamedPolygon('C108_1') Or  IsNamedPolygon('5Vp') Or  IsNamedPolygon('T200_4') Or  IsNamedPolygon('12Vp') Or  IsNamedPolygon('T200_6') Or  IsNamedPolygon('C108_1') Or  IsNamedPolygon('SGND')] p19: connectstyle=Direct reliefconductorwidth=10 reliefentries=4 polygonreliefangle="90 Angle" airgapwidth=10
PolygonConnect PolygonConnect_40 [All vs IsNamedPolygon('Neutral')] p20: connectstyle=Direct reliefconductorwidth=10 reliefentries=4 polygonreliefangle="90 Angle" airgapwidth=10
PolygonConnect PolygonConnect_39 [All vs IsNamedPolygon('12Vp')] p21: connectstyle=Direct reliefconductorwidth=10 reliefentries=4 polygonreliefangle="90 Angle" airgapwidth=10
